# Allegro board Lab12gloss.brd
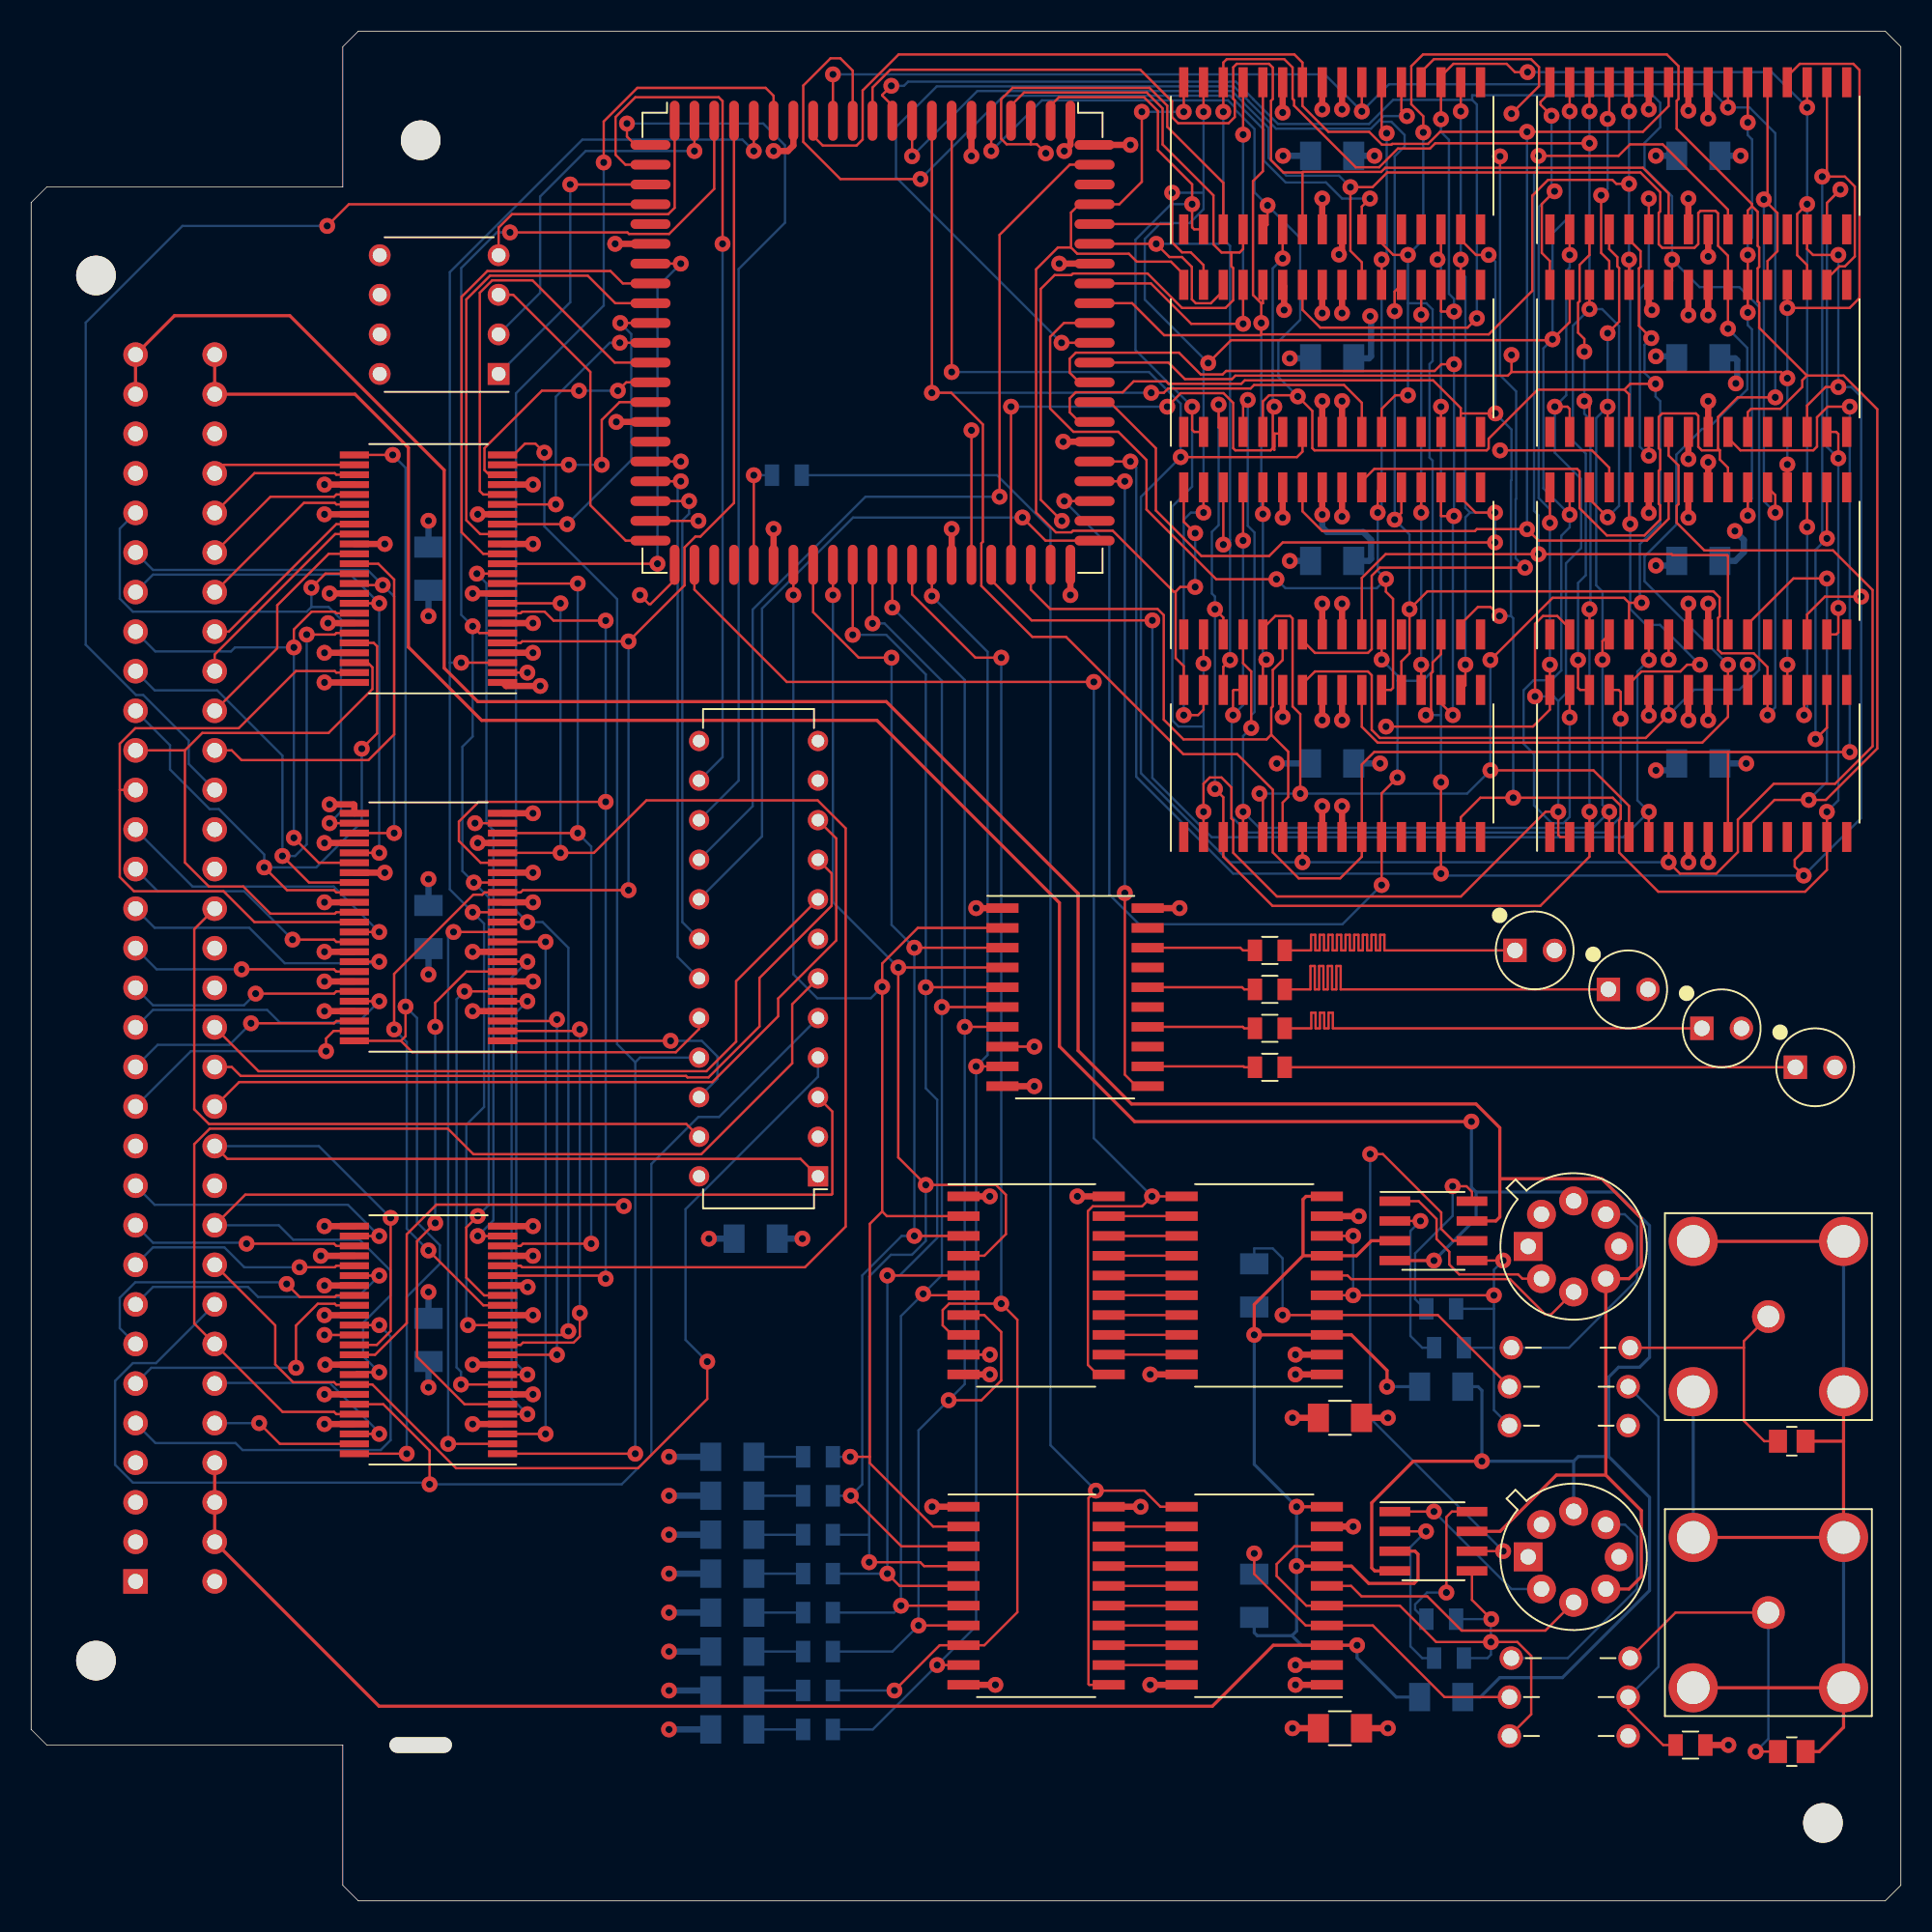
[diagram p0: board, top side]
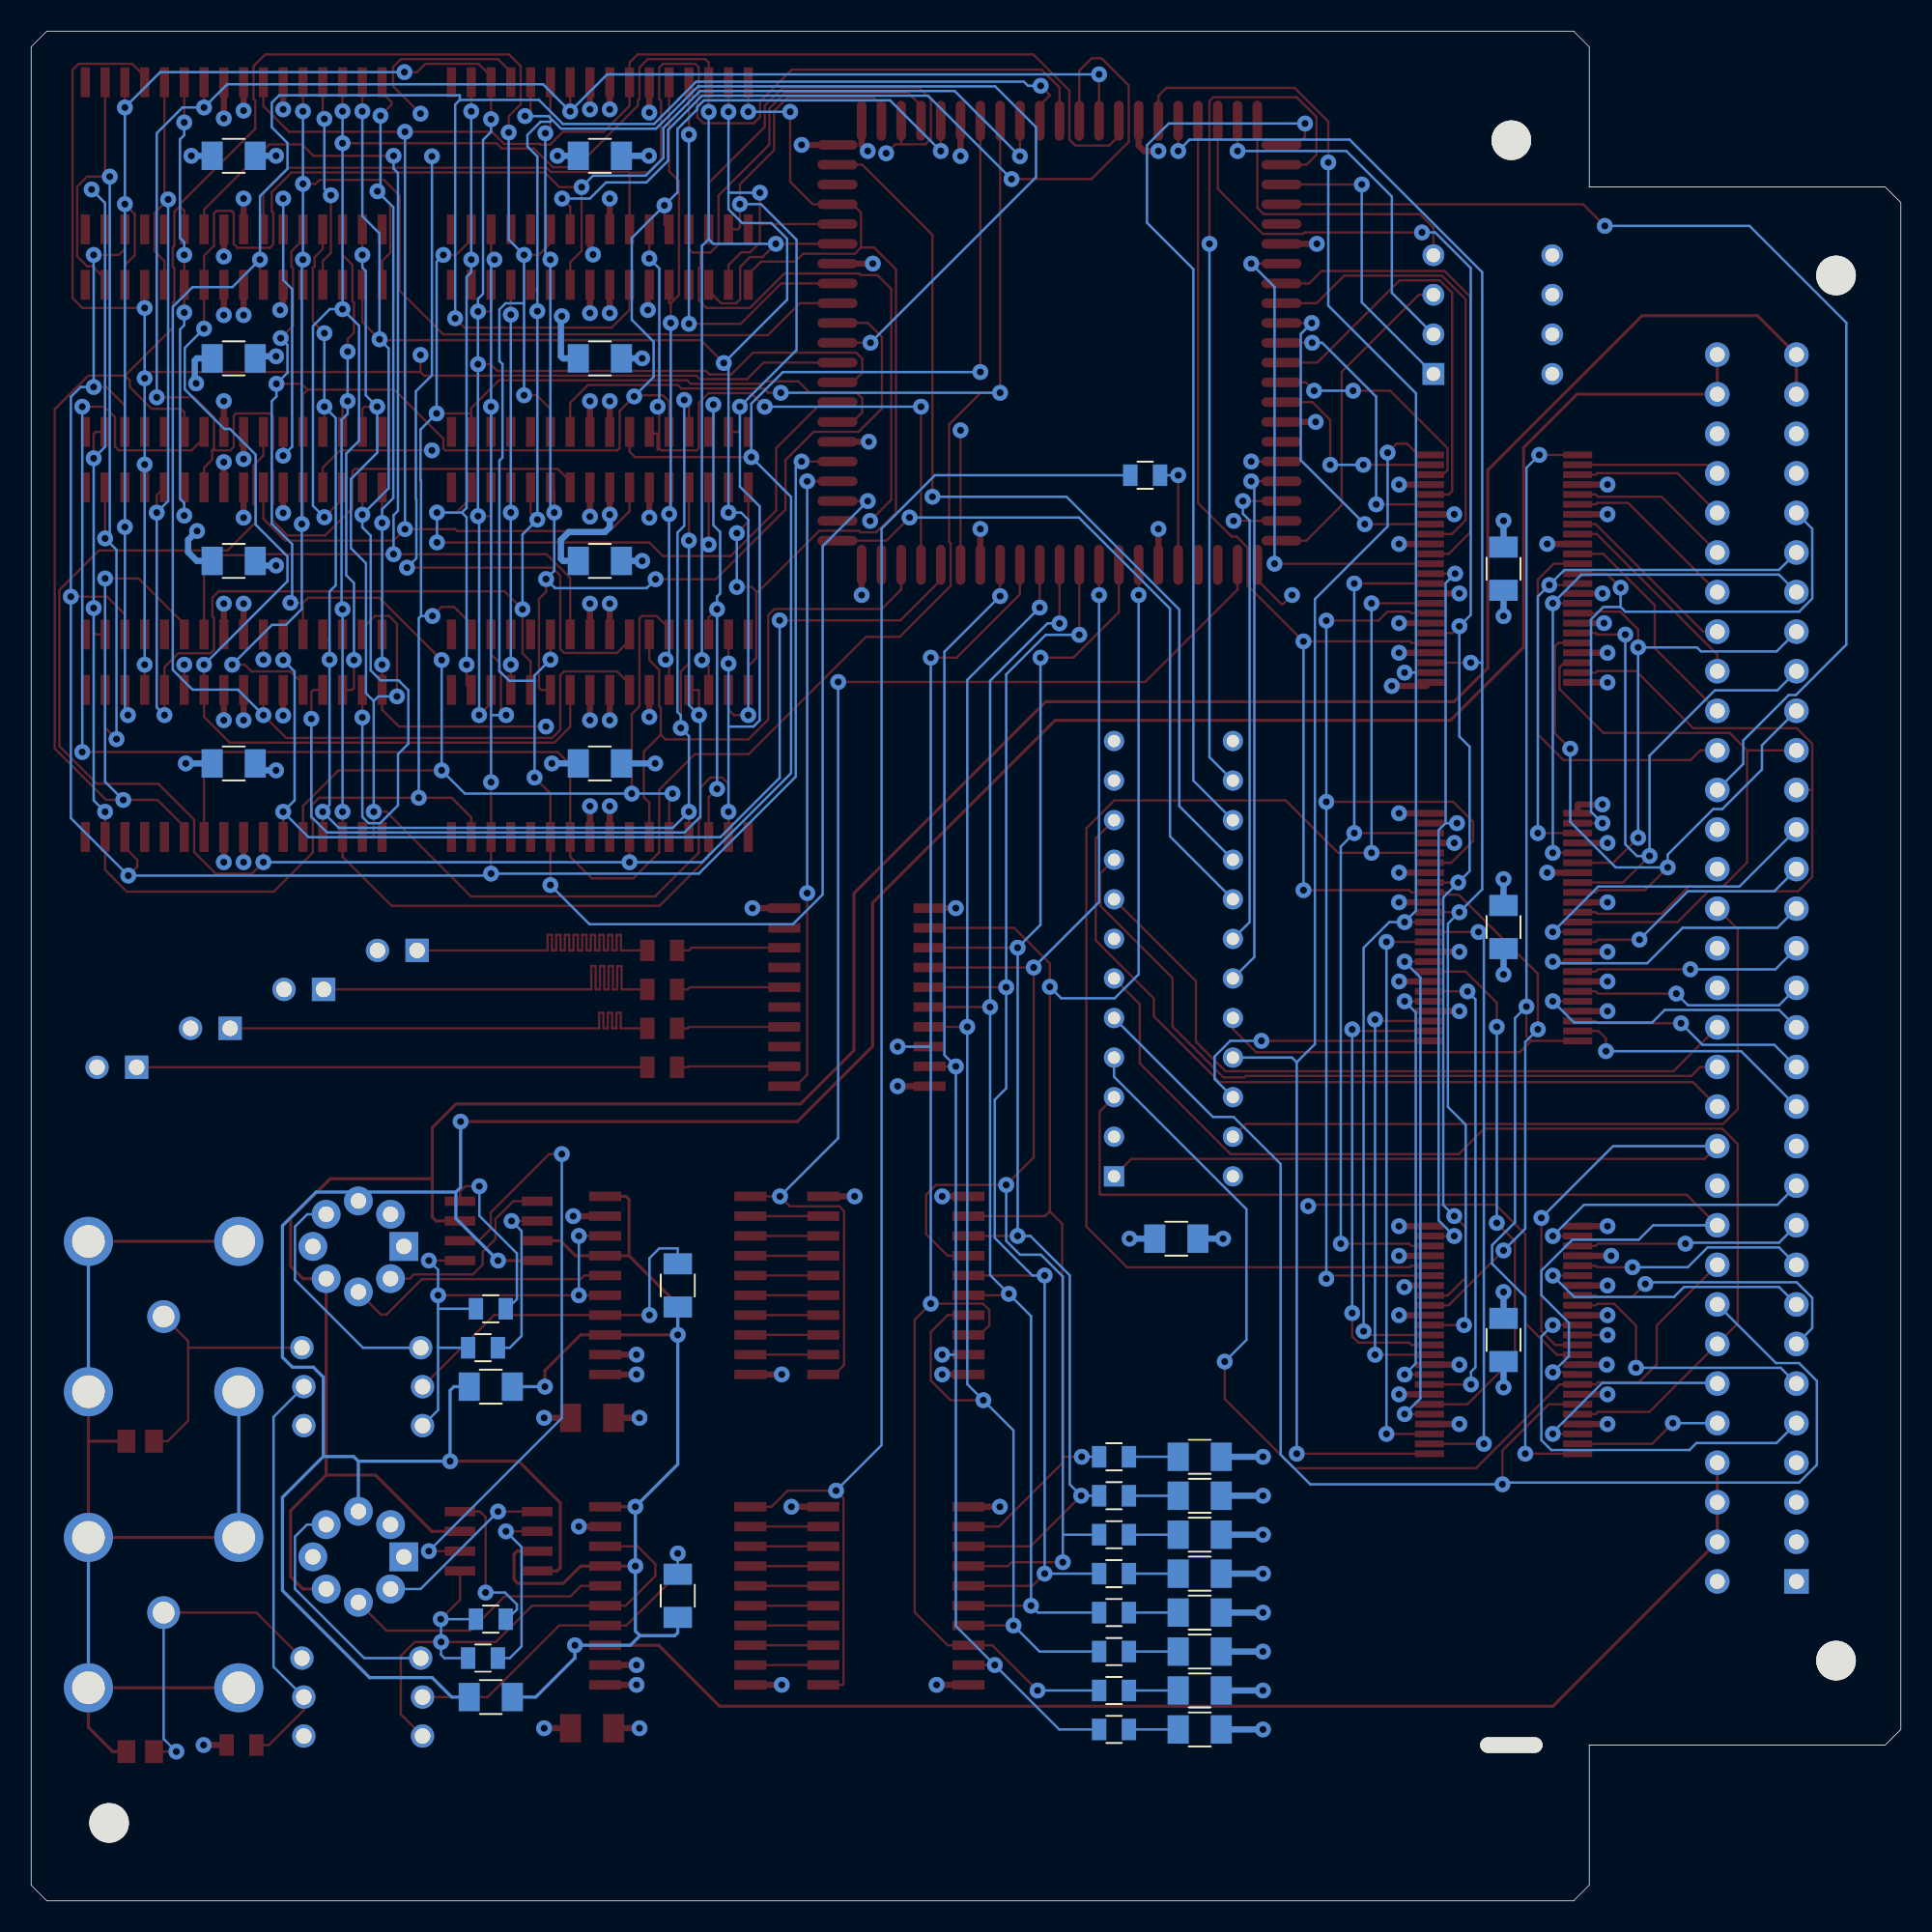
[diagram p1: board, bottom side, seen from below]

Outline 120 x 120 mm; copper layers: TOP, GND, VCC, BOTTOM. Coordinates in mm from the lower left corner of the outline.

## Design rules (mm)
constraint set DEFAULT: min track width 0.15
net group LEDNETS: nets LED1 LED2 LED3 LED4
net group MEMORY[0..28]: nets MEMORY.RA0 MEMORY.RA1 MEMORY.RA2 MEMORY.RA3 MEMORY.RA4 MEMORY.RA5 MEMORY.RA6 MEMORY.RA7 MEMORY.RA8 MEMORY.RA9 MEMORY.RA10 MEMORY.RA11 MEMORY.RA12 MEMORY.RA13 MEMORY.RA14 MEMORY.RA15 MEMORY.RCS0 MEMORY.RCS1 MEMORY.RCS2 MEMORY.RCS3 MEMORY.RD0 MEMORY.RD1 MEMORY.RD2 MEMORY.RD3 MEMORY.RD4 MEMORY.RD5 MEMORY.RD6 MEMORY.RD7 MEMORY.RWE
net group POWER: nets AGND GND_EARTH V12N V+12
nets with their own width: min track width 0.4; nets GND VCC

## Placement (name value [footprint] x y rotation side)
C1  0.1uF  [CAPC3216X110N]  25.5 36 90 bottom
C2  0.1uF  [CAPC3216X110N]  46.5 42.5 0 bottom
C3  0.1uF  [CAPC3216X110N]  25.5 62.5 90 bottom
C4  0.1uF  [CAPC3216X110N]  25.5 85.5 90 bottom
C5  47PF  [CAPC2012X110N]  113 29.5 0 top
C6  47PF  [CAPC2012X110N]  113 9.58 0 top
C7  0.01u  [CAPC3216X110N]  84 31 0 top
C8  0.01u  [CAPC3216X110N]  78.5 39.5 270 bottom
C9  0.1u  [CAPC3216X110N]  90.5 33 180 bottom
C10  0.01u  [CAPC3216X110N]  84 11.08 0 top
C11  0.01u  [CAPC3216X110N]  78.5 19.58 270 bottom
C12  0.1u  [CAPC3216X110N]  90.5 13.08 180 bottom
C13  330p  [CAPC3216X110N]  45 13.5 180 bottom
C14  330p  [CAPC3216X110N]  45 18.5 180 bottom
C15  330p  [CAPC3216X110N]  45 23.5 180 bottom
C16  330p  [CAPC3216X110N]  45 28.5 180 bottom
C17  330p  [CAPC3216X110N]  45 11 180 bottom
C18  330p  [CAPC3216X110N]  45 16 180 bottom
C19  330p  [CAPC3216X110N]  45 21 180 bottom
C20  330p  [CAPC3216X110N]  45 26 180 bottom
C21  0.1uF  [CAPC3216X110N]  83.5 112 0 bottom
C22  0.1uF  [CAPC3216X110N]  107 112 0 bottom
C23  0.1uF  [CAPC3216X110N]  83.5 99 0 bottom
C24  0.1uF  [CAPC3216X110N]  107 99 0 bottom
C25  0.1uF  [CAPC3216X110N]  83.5 86 0 bottom
C26  0.1uF  [CAPC3216X110N]  107 86 0 bottom
C27  0.1uF  [CAPC3216X110N]  107 73 0 bottom
C28  0.1uF  [CAPC3216X110N]  83.5 73 0 bottom
D1  LED  [LEDRD254W00D500H860P]  96.5 61 0 top
D2  LED  [LEDRD254W00D500H860P]  102.5 58.5 0 top
D3  LED  [LEDRD254W00D500H860P]  108.5 56 0 top
D4  LED  [LEDRD254W00D500H860P]  114.5 53.5 0 top
J1  CON64  [DIN64]  6.7 20.5 0 top
J2  BNC  [CONNEX_112659]  111.5 37.5 0 top
J3  BNC  [CONNEX_112659]  111.5 18.5 0 top
L1  47u  [INDAD762W79L381D254P]  95 35.5 0 top
L2  47u  [INDAD762W79L381D254P]  95 15.58 0 top
L3  47u  [INDAD762W79L381D254P]  102.5 33 180 top
L4  47u  [INDAD762W79L381D254P]  102.5 30.5 180 top
L5  47u  [INDAD762W79L381D254P]  102.5 13.08 180 top
L6  47u  [INDAD762W79L381D254P]  102.5 10.58 180 top
NOREF  -  []  119.5 119.5 0 top
NOREF#2  -  []  37.5 0 90 top
NOREF#3  -  []  -74.06 -89.06 0 top
NOREF#4  -  []  25 10 90 top
NOREF#5  -  []  25 10 90 top
NOREF#6  -  []  25 10 0 top
NOREF#7  -  []  25 10 0 top
NOREF#8  -  []  25 10 90 top
NOREF#9  -  []  197.72 157.32 0 top
NOREF#10  -  [unnamed#2]  25 10 0 top
R1  150  [RESC2012X60N]  79.5 61 0 top
R2  150  [RESC2012X60N]  79.5 58.5 0 top
R3  150  [RESC2012X60N]  79.5 56 0 top
R4  150  [RESC2012X60N]  79.5 53.5 0 top
R5  2K  [RESC2012X60N]  48.5 91.5 0 bottom
R6  100  [RESC2012X60N]  90.5 38 180 bottom
R7  100  [RESC2012X60N]  91 35.5 180 bottom
R8  100  [RESC2012X60N]  90.5 18.08 180 bottom
R9  100  [RESC2012X60N]  91 15.58 180 bottom
R10  10K  [RESC2012X60N]  50.5 13.5 0 bottom
R11  10K  [RESC2012X60N]  50.5 18.5 0 bottom
R12  10K  [RESC2012X60N]  50.5 23.5 0 bottom
R13  10K  [RESC2012X60N]  50.5 28.5 0 bottom
R14  10K  [RESC2012X60N]  50.5 11 0 bottom
R15  10K  [RESC2012X60N]  50.5 16 0 bottom
R16  10K  [RESC2012X60N]  50.5 21 0 bottom
R17  10K  [RESC2012X60N]  50.5 26 0 bottom
R18  10K  [RESC2012X60N]  106.5 10 0 top
U1  FCT16245  [SOP63P1035X279-48N]  25.5 36 90 top
U2  20L10  [DIP763W46P254L3204H508Q24P]  50.5 46.5 90 top
U3  FCT16245  [SOP63P1035X279-48N]  25.5 62.5 90 top
U4  FCT16245  [SOP63P1035X279-48N]  25.5 85.5 90 top
U5  EPF8282A_LCC  [PLCC127P3022X3022X457-84N]  54 100 270 top
U6  74ACT574  [SOIC127P1034X264-20N]  67 58 270 top
U7  EPC1064  [DIP763W46P254L991H419Q8P]  30 98 90 top
U8  TLC5602A  [SOIC127P1034X264-20N]  78.5 39.5 90 top
U9  TLE2037A  [TO292P469H584-8P]  99 42 0 top
U10  DG419AK  [SOIC127P600X175-8N]  90 43 270 top
U11  TLC5602A  [SOIC127P1034X264-20N]  78.5 19.58 90 top
U12  TLE2037A  [TO292P469H584-8P]  99 22.08 0 top
U13  DG419AK  [SOIC127P600X175-8N]  90 23.08 270 top
U14  74ACT574  [SOIC127P1034X264-20N]  64.5 39.5 270 top
U15  74ACT574  [SOIC127P1034X264-20N]  64.5 19.58 270 top
U16  TC55B4257  [SOIC127P1032X265-32N]  83.5 73 0 top
U17  TC55B4257  [SOIC127P1032X265-32N]  83.5 86 0 top
U18  TC55B4257  [SOIC127P1032X265-32N]  83.5 99 0 top
U19  TC55B4257  [SOIC127P1032X265-32N]  83.5 112 0 top
U20  TC55B4257  [SOIC127P1032X265-32N]  107 73 0 top
U21  TC55B4257  [SOIC127P1032X265-32N]  107 86 0 top
U22  TC55B4257  [SOIC127P1032X265-32N]  107 99 0 top
U23  TC55B4257  [SOIC127P1032X265-32N]  107 112 0 top

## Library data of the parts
C1-C4 C13-C20 = CAP NP
C5 C7-C9 = CAP NP: room: CHAN1
C6 C10-C12 = CAP NP: room: CHAN2
C21-C28 = CAP NP: room: MEM
D1-D4 = PHOTODIODE_0
J1 = CON64
J2 = BNC: room: CHAN1
J3 = BNC: room: CHAN2
L1 L3 L4 = INDUCTOR: room: CHAN1
L2 L5 L6 = INDUCTOR: room: CHAN2
R1-R4 = R: room: LED
R5 R10-R17 = R
R6 R7 = R: room: CHAN1
R8 R9 R18 = R: room: CHAN2
U1 U3 U4 = FCT16245
U2 = 20L10: alternate symbols: (T:SOIC24;B:SOIC24_PE)
U5 = EPF8282A/LCC
U6 = 74ACT574: room: LED
U7 = EPC1064
U8 = TLC5602A: room: CHAN1
U9 = TLE2037A: room: CHAN1
U10 = DG419AK: room: CHAN1
U11 = TLC5602A: room: CHAN2
U12 = TLE2037A: room: CHAN2
U13 = DG419AK: room: CHAN2
U14 = 74ACT574: room: CHAN1
U15 = 74ACT574: room: CHAN2
U16-U23 = TC55B4257: room: MEM

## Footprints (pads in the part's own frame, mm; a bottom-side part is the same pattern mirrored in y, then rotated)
CAPC2012X110N
  rect 1.15x1.47 smd: 1(-0.885,0) 2(0.885,0)
CAPC3216X110N
  rect 1.35x1.82 smd: 1(-1.385,0) 2(1.385,0)
CONNEX_112659
  round 2.1 hole 1.4: 1(0,0)
  round 3.15 hole 2.1: 2(-4.825,4.825) 3(4.825,4.825) 4(4.825,-4.825) 5(-4.825,-4.825)
DIN64
  round 2.54 hole 2.794 unplated: (-2.54,83.82) (-2.54,-5.08)
  rect 1.575x1.575 hole 0.965: 1(0,0)
  round 1.575 hole 0.965: 2(0,2.54) 3(0,5.08) 4(0,7.62) 5(0,10.16) 6(0,12.7) 7(0,15.24) 8(0,17.78) 9(0,20.32) 10(0,22.86) 11(0,25.4) 12(0,27.94) 13(0,30.48) 14(0,33.02) 15(0,35.56) 16(0,38.1) 17(0,40.64) 18(0,43.18) 19(0,45.72) 20(0,48.26) 21(0,50.8) 22(0,53.34) 23(0,55.88) 24(0,58.42) 25(0,60.96) 26(0,63.5) 27(0,66.04) 28(0,68.58) 29(0,71.12) 30(0,73.66) 31(0,76.2) 32(0,78.74) 33(5.08,0) 34(5.08,2.54) 35(5.08,5.08) 36(5.08,7.62) 37(5.08,10.16) 38(5.08,12.7) 39(5.08,15.24) 40(5.08,17.78) 41(5.08,20.32) 42(5.08,22.86) 43(5.08,25.4) 44(5.08,27.94) 45(5.08,30.48) 46(5.08,33.02) 47(5.08,35.56) 48(5.08,38.1) 49(5.08,40.64) 50(5.08,43.18) 51(5.08,45.72) 52(5.08,48.26) 53(5.08,50.8) 54(5.08,53.34) 55(5.08,55.88) 56(5.08,58.42) 57(5.08,60.96) 58(5.08,63.5) 59(5.08,66.04) 60(5.08,68.58) 61(5.08,71.12) 62(5.08,73.66) 63(5.08,76.2) 64(5.08,78.74)
DIP763W46P254L991H419Q8P
  rect 1.4x1.4 hole 0.9: 1(0,0)
  round 1.4 hole 0.9: 2(2.54,0) 3(5.08,0) 4(7.62,0) 5(7.62,7.63) 6(5.08,7.63) 7(2.54,7.63) 8(0,7.63)
DIP763W46P254L3204H508Q24P
  rect 1.3x1.3 hole 0.8: 1(0,0)
  round 1.3 hole 0.8: 2(2.54,0) 3(5.08,0) 4(7.62,0) 5(10.16,0) 6(12.7,0) 7(15.24,0) 8(17.78,0) 9(20.32,0) 10(22.86,0) 11(25.4,0) 12(27.94,0) 13(27.94,7.63) 14(25.4,7.63) 15(22.86,7.63) 16(20.32,7.63) 17(17.78,7.63) 18(15.24,7.63) 19(12.7,7.63) 20(10.16,7.63) 21(7.62,7.63) 22(5.08,7.63) 23(2.54,7.63) 24(0,7.63)
INDAD762W79L381D254P
  round 1.5 hole 1: 1(0,0) 2(7.62,0)
LEDRD254W00D500H860P
  round 1.5 hole 1: A(1.27,0)
  rect 1.5x1.5 hole 1: C(-1.27,0)
PLCC127P3022X3022X457-84N
  oval 2.57x0.62 smd: 1(-14.25,0) 2(-14.25,-1.27) 3(-14.25,-2.54) 4(-14.25,-3.81) 5(-14.25,-5.08) 6(-14.25,-6.35) 7(-14.25,-7.62) 8(-14.25,-8.89) 9(-14.25,-10.16) 10(-14.25,-11.43) 11(-14.25,-12.7) 33(14.25,-12.7) 34(14.25,-11.43) 35(14.25,-10.16) 36(14.25,-8.89) 37(14.25,-7.62) 38(14.25,-6.35) 39(14.25,-5.08) 40(14.25,-3.81) 41(14.25,-2.54) 42(14.25,-1.27) 43(14.25,0) 44(14.25,1.27) 45(14.25,2.54) 46(14.25,3.81) 47(14.25,5.08) 48(14.25,6.35) 49(14.25,7.62) 50(14.25,8.89) 51(14.25,10.16) 52(14.25,11.43) 53(14.25,12.7) 75(-14.25,12.7) 76(-14.25,11.43) 77(-14.25,10.16) 78(-14.25,8.89) 79(-14.25,7.62) 80(-14.25,6.35) 81(-14.25,5.08) 82(-14.25,3.81) 83(-14.25,2.54) 84(-14.25,1.27)
  oval 0.62x2.57 smd: 12(-12.7,-14.25) 13(-11.43,-14.25) 14(-10.16,-14.25) 15(-8.89,-14.25) 16(-7.62,-14.25) 17(-6.35,-14.25) 18(-5.08,-14.25) 19(-3.81,-14.25) 20(-2.54,-14.25) 21(-1.27,-14.25) 22(0,-14.25) 23(1.27,-14.25) 24(2.54,-14.25) 25(3.81,-14.25) 26(5.08,-14.25) 27(6.35,-14.25) 28(7.62,-14.25) 29(8.89,-14.25) 30(10.16,-14.25) 31(11.43,-14.25) 32(12.7,-14.25) 54(12.7,14.25) 55(11.43,14.25) 56(10.16,14.25) 57(8.89,14.25) 58(7.62,14.25) 59(6.35,14.25) 60(5.08,14.25) 61(3.81,14.25) 62(2.54,14.25) 63(1.27,14.25) 64(0,14.25) 65(-1.27,14.25) 66(-2.54,14.25) 67(-3.81,14.25) 68(-5.08,14.25) 69(-6.35,14.25) 70(-7.62,14.25) 71(-8.89,14.25) 72(-10.16,14.25) 73(-11.43,14.25) 74(-12.7,14.25)
RESC2012X60N
  rect 0.92x1.38 smd: 1(-0.955,0) 2(0.955,0)
SOIC127P600X175-8N
  rect 0.6x1.97 smd: 1(-1.905,-2.475) 2(-0.635,-2.475) 3(0.635,-2.475) 4(1.905,-2.475) 5(1.905,2.475) 6(0.635,2.475) 7(-0.635,2.475) 8(-1.905,2.475)
SOIC127P1032X265-32N
  rect 0.59x1.92 smd: 1(-9.525,-4.72) 2(-8.255,-4.72) 3(-6.985,-4.72) 4(-5.715,-4.72) 5(-4.445,-4.72) 6(-3.175,-4.72) 7(-1.905,-4.72) 8(-0.635,-4.72) 9(0.635,-4.72) 10(1.905,-4.72) 11(3.175,-4.72) 12(4.445,-4.72) 13(5.715,-4.72) 14(6.985,-4.72) 15(8.255,-4.72) 16(9.525,-4.72) 17(9.525,4.72) 18(8.255,4.72) 19(6.985,4.72) 20(5.715,4.72) 21(4.445,4.72) 22(3.175,4.72) 23(1.905,4.72) 24(0.635,4.72) 25(-0.635,4.72) 26(-1.905,4.72) 27(-3.175,4.72) 28(-4.445,4.72) 29(-5.715,4.72) 30(-6.985,4.72) 31(-8.255,4.72) 32(-9.525,4.72)
SOIC127P1034X264-20N
  rect 0.61x2.06 smd: 1(-5.715,-4.66) 2(-4.445,-4.66) 3(-3.175,-4.66) 4(-1.905,-4.66) 5(-0.635,-4.66) 6(0.635,-4.66) 7(1.905,-4.66) 8(3.175,-4.66) 9(4.445,-4.66) 10(5.715,-4.66) 11(5.715,4.66) 12(4.445,4.66) 13(3.175,4.66) 14(1.905,4.66) 15(0.635,4.66) 16(-0.635,4.66) 17(-1.905,4.66) 18(-3.175,4.66) 19(-4.445,4.66) 20(-5.715,4.66)
SOP63P1035X279-48N
  rect 0.44x1.87 smd: 1(-7.302,-4.755) 2(-6.668,-4.755) 3(-6.032,-4.755) 4(-5.398,-4.755) 5(-4.762,-4.755) 6(-4.128,-4.755) 7(-3.492,-4.755) 8(-2.858,-4.755) 9(-2.222,-4.755) 10(-1.588,-4.755) 11(-0.952,-4.755) 12(-0.318,-4.755) 13(0.318,-4.755) 14(0.952,-4.755) 15(1.588,-4.755) 16(2.222,-4.755) 17(2.858,-4.755) 18(3.492,-4.755) 19(4.128,-4.755) 20(4.762,-4.755) 21(5.398,-4.755) 22(6.032,-4.755) 23(6.668,-4.755) 24(7.302,-4.755) 25(7.302,4.755) 26(6.668,4.755) 27(6.032,4.755) 28(5.398,4.755) 29(4.762,4.755) 30(4.128,4.755) 31(3.492,4.755) 32(2.858,4.755) 33(2.222,4.755) 34(1.588,4.755) 35(0.952,4.755) 36(0.318,4.755) 37(-0.318,4.755) 38(-0.952,4.755) 39(-1.588,4.755) 40(-2.222,4.755) 41(-2.858,4.755) 42(-3.492,4.755) 43(-4.128,4.755) 44(-4.762,4.755) 45(-5.398,4.755) 46(-6.032,4.755) 47(-6.668,4.755) 48(-7.302,4.755)
TO292P469H584-8P
  rect 1.85x1.85 hole 1: 1(-2.921,0)
  round 1.85 hole 1: 2(-2.066,-2.066) 3(0,-2.921) 4(2.066,-2.066) 5(2.921,0) 6(2.066,2.066) 7(0,2.921) 8(-2.066,2.066)
unnamed#2
  round 2.54 hole 2.794 unplated: (0,103) (90,-5)
  oval 4x1 hole 5x1.5 unplated: (0,0)

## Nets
AGND: C8.2 C9.2 C11.2 C12.2 J1.34 J1.35 J1.36 U8.3 U8.7 U8.10 U10.3 U11.3 U11.7 U11.10 U13.3
GND: C1.2 C2.2 C3.2 C4.2 C7.2 C10.2 C13.2 C14.2 C15.2 C16.2 C17.2 C18.2 C19.2 C20.2 C21.2 C22.2 C23.2 C24.2 C25.2 C26.2 C27.2 C28.2 J1.1 J1.2 J1.3 J1.33 R18.2 U1.4 U1.10 U1.15 U1.21 U1.24 U1.25(G\) U1.28 U1.34 U1.39 U1.45 U2.11 U2.12 U2.13 U3.4 U3.10 U3.15 U3.21 U3.24 U3.25(G\) U3.28 U3.34 U3.39 U3.45 U4.1 U4.4 U4.10 U4.15 U4.21 U4.28 U4.34 U4.39 U4.45 U4.48 U5.5 U5.26 U5.47 U5.53 U5.68 U5.74 U5.75 U6.1 U6.10 U7.5 U8.1 U8.20 U11.1 U11.20 U14.1 U14.10 U15.1 U15.10 U16.9 U16.25 U16.27 U17.9 U17.25 U17.27 U18.9 U18.25 U18.27 U19.9 U19.25 U19.27 U20.9 U20.25 U20.27 U21.9 U21.25 U21.27 U22.9 U22.25 U22.27 U23.9 U23.25 U23.27
GND_EARTH: C5.2 C6.2 J2.2 J2.3 J2.4 J2.5(GND5) J3.2 J3.3 J3.4 J3.5(GND5)
V12N: J1.31 J1.32 U9.4(V-) U10.7 U12.4(V-) U13.7
VCC: C1.1 C2.1 C3.1 C4.1 C7.1 C10.1 C21.1 C22.1 C23.1 C24.1 C25.1 C26.1 C27.1 C28.1 D1.A D2.A D3.A D4.A J1.29 J1.30 J1.62 L4.1 L6.1 U1.7 U1.18 U1.31 U1.42 U2.24(VCC) U3.7 U3.18 U3.31 U3.42 U4.7 U4.18 U4.31 U4.42 U5.17 U5.38 U5.59 U5.80 U6.20 U7.7 U7.8 U8.2 U8.9(VD2) U11.2 U11.9(VD2) U14.20 U15.20 U16.8 U16.24 U17.8 U17.24 U18.8 U18.24 U19.8 U19.24 U20.8 U20.24 U21.8 U21.24 U22.8 U22.24 U23.8 U23.24
A0: J1.54 U4.36
A1: J1.55 U4.35
A2: J1.56 U4.33
A3: J1.57 U4.32
A4: J1.58 U4.30
A5: J1.59 U4.29
A6: J1.60 U4.27
A7: J1.61 U4.26
A8: J1.13 U3.47
A9: J1.14 U3.46
A10: J1.15 U3.44
A11: J1.16 U3.43
A12: J1.17 U3.41
A13: J1.18 U3.40
A14: J1.19 U3.38
A15: J1.20 U3.37
A16: J1.37 U1.47
A17: J1.38 U1.46
A18: J1.39 U1.44 U2.6
A19: J1.40 U1.43 U2.5
A20: J1.41 U1.41 U2.4
A21: J1.42 U1.40 U2.3
A22: J1.43 U1.38 U2.2
A23: J1.44 U1.37 U2.1
AEN: J1.47 U2.8
BA0: U1.13 U3.13 U4.2 U5.6
BA1: U1.14 U3.14 U4.3 U5.7
BA2: U1.16 U3.16 U4.5 U5.8
BA3: U1.17 U3.17 U4.6 U5.9
BA4: U1.19 U3.19 U4.8
BA5: U1.20 U3.20 U4.9
BA6: U1.22 U3.22 U4.11
BA7: U1.23 U3.23 U4.12
BD0: U4.23 U5.25
BD1: U4.22 U5.24
BD2: U4.20 U5.23
BD3: U4.19 U5.22
BD4: U4.17 U5.21
BD5: U4.16 U5.20
BD6: U4.14 U5.19
BD7: U4.13 U5.18
BD8: U1.12 U3.2
BD9: U1.11 U3.3
BD10: U1.9 U3.5
BD11: U1.8 U3.6
BD12: U1.6 U3.8
BD13: U1.5 U3.9
BD14: U1.3 U3.11
BD15: U1.2 U3.12
BNC2: C5.1 J2.1 L1.2
BNC3: C6.1 J3.1 L2.2
BRD: U2.16 U5.73
BRESET: U2.15 U5.12
BWR: U2.17 U5.54
D0: J1.28 U3.26 U4.37
D1: J1.27 U3.27 U4.38
D2: J1.26 U3.29 U4.40
D3: J1.25 U3.30 U4.41
D4: J1.24 U3.32 U4.43
D5: J1.23 U3.33 U4.44
D6: J1.22 U3.35 U4.46
D7: J1.21 U3.36 U4.47
D8: J1.4 U1.36
D9: J1.5 U1.35
D10: J1.6 U1.33
D11: J1.7 U1.32
D12: J1.8 U1.30
D13: J1.9 U1.29
D14: J1.10 U1.27
D15: J1.11 U1.26
DATA: U5.14 U7.1
DCLK: U5.10 U7.2
DDIR: U1.48 U2.20 U3.48 U4.25(G\)
DEN: U1.1 U2.21 U4.24
DHEN: U2.22 U3.1
FPGA: U2.18 U5.30
GAIN: U5.28 U10.6 U13.6
HS: U2.19 U5.29
LED1: D1.C(CATHODE) R1.2
LED2: D2.C(CATHODE) R2.2
LED3: D3.C(CATHODE) R3.2
LED4: D4.C(CATHODE) R4.2
MCLK: J1.52 U5.31
MEMORY.RA0: U5.79 U16.5 U17.5 U18.5 U19.5 U20.5 U21.5 U22.5 U23.5
MEMORY.RA1: U5.78 U16.4 U17.4 U18.4 U19.4 U20.4 U21.4 U22.4 U23.4
MEMORY.RA2: U5.77 U16.3 U17.3 U18.3 U19.3 U20.3 U21.3 U22.3 U23.3
MEMORY.RA3: U5.76 U16.2 U17.2 U18.2 U19.2 U20.2 U21.2 U22.2 U23.2
MEMORY.RA4: U5.71 U16.32 U17.32 U18.32 U19.32 U20.32 U21.32 U22.32 U23.32
MEMORY.RA5: U5.70 U16.31 U17.31 U18.31 U19.31 U20.31 U21.31 U22.31 U23.31
MEMORY.RA6: U5.69 U16.30 U17.30 U18.30 U19.30 U20.30 U21.30 U22.30 U23.30
MEMORY.RA7: U5.67 U16.29 U17.29 U18.29 U19.29 U20.29 U21.29 U22.29 U23.29
MEMORY.RA8: U5.66 U16.28 U17.28 U18.28 U19.28 U20.28 U21.28 U22.28 U23.28
MEMORY.RA9: U5.65 U16.22 U17.22 U18.22 U19.22 U20.22 U21.22 U22.22 U23.22
MEMORY.RA10: U5.64 U16.21 U17.21 U18.21 U19.21 U20.21 U21.21 U22.21 U23.21
MEMORY.RA11: U5.63 U16.20 U17.20 U18.20 U19.20 U20.20 U21.20 U22.20 U23.20
MEMORY.RA12: U5.62 U16.19 U17.19 U18.19 U19.19 U20.19 U21.19 U22.19 U23.19
MEMORY.RA13: U5.61 U16.18 U17.18 U18.18 U19.18 U20.18 U21.18 U22.18 U23.18
MEMORY.RA14: U5.60 U16.15 U17.15 U18.15 U19.15 U20.15 U21.15 U22.15 U23.15
MEMORY.RA15: U5.58 U16.14 U17.14 U18.14 U19.14 U20.14 U21.14 U22.14 U23.14
MEMORY.RCS0: U5.51 U16.6 U17.6
MEMORY.RCS1: U5.50 U18.6 U19.6
MEMORY.RCS2: U5.49 U20.6 U21.6
MEMORY.RCS3: U5.48 U22.6 U23.6
MEMORY.RD0: U5.81 U16.7 U18.7 U20.7 U22.7
MEMORY.RD1: U5.82 U16.10 U18.10 U20.10 U22.10
MEMORY.RD2: U5.83 U16.23 U18.23 U20.23 U22.23
MEMORY.RD3: U5.84 U16.26 U18.26 U20.26 U22.26
MEMORY.RD4: U5.1 U17.7 U19.7 U21.7 U23.7
MEMORY.RD5: U5.2 U17.10 U19.10 U21.10 U23.10
MEMORY.RD6: U5.3 U17.23 U19.23 U21.23 U23.23
MEMORY.RD7: U5.4 U17.26 U19.26 U21.26 U23.26
MEMORY.RWE: U5.56 U16.11(W\E\) U17.11(W\E\) U18.11(W\E\) U19.11(W\E\) U20.11(W\E\) U21.11(W\E\) U22.11(W\E\) U23.11(W\E\)
MRD: J1.46 U2.9
MWR: J1.45 U2.10
N00036_DATA_DAAMP: L4.2 R6.1 R7.1 U8.5 U8.8 U10.5(VL)
N00036_DATA_DAAMP1: L6.2 R8.1 R9.1 U11.5 U11.8 U13.5(VL)
N00038_DATA_DAAMP: C8.1 L3.2 U8.4
N00038_DATA_DAAMP1: C11.1 L5.2 U11.4
N00044_DATA_DAAMP: U9.2 U10.1
N00044_DATA_DAAMP1: U12.2 U13.1
N00060_DATA_DAAMP: U8.6 U9.3
N00060_DATA_DAAMP1: U11.6 U12.3
N282866_DATA_DAAMP: R6.2 U10.8
N282866_DATA_DAAMP1: R8.2 U13.8
N282912_DATA_DAAMP: R7.2 U10.2
N282912_DATA_DAAMP1: R9.2 U13.2
NCS: U5.11 U7.4
OE: U5.32 U7.3(OE)
OUTA: L1.1 U9.6
OUTB: L2.1 U12.6
Q0: R1.1 U6.18
Q1: R2.1 U6.16
Q2: R3.1 U6.14
Q3: R4.1 U6.12(Q8)
RDY: J1.50 U2.23
RESET: J1.53 U5.15
SEL: U2.14 U5.13
V+12: C9.1 C12.1 J1.63 J1.64 U9.7 U10.4 U12.7 U13.4
VCLKA: U5.34 U8.11 U14.11
VCLKC: R5.2 U11.11 U15.11
VD0: R13.2 U5.39 U6.2 U14.2 U15.2
VD1: R17.2 U5.40 U6.3 U14.3 U15.3
VD2: R12.2 U5.41 U6.4 U14.4 U15.4
VD3: R16.2 U5.42 U6.5 U14.5 U15.5
VD4: R11.2 U5.43 U6.6 U14.6 U15.6
VD5: R15.2 U5.44 U6.7 U14.7 U15.7
VD6: R10.2 U5.45 U6.8 U14.8 U15.8
VD7: R14.2 U5.46(VD7) U6.9 U14.9 U15.9
VREF: L3.1 L5.1 R18.1
WAIT: J1.51 U5.33
WSTAT: U5.57 U6.11
N14843: C19.1 R16.1
N14849: C15.1 R12.1
N14853: C20.1 R17.1
N14855: C16.1 R13.1
N15143: C17.1 R14.1
N15151: C13.1 R10.1
N15155: C18.1 R15.1
N15161: C14.1 R11.1
N58063: U8.12 U14.19
N58118: U8.13 U14.18
N58173: U8.14 U14.17
N58228: U8.15 U14.16
N58283: U8.16 U14.15
N58338: U8.17 U14.14
N58393: U8.18 U14.13
N58448: U8.19 U14.12(Q8)
N58834: U11.12 U15.19
N58889: U11.13 U15.18
N58944: U11.14 U15.17
N58999: U11.15 U15.16
N59054: U11.16 U15.15
N59109: U11.17 U15.14
N59164: U11.18 U15.13
N59219: U11.19 U15.12(Q8)
N409523: R5.1 U5.37

Pads without a net: J1 12 48 49; U2 7; U5 16 27 35 36 52 55 72; U6 13 15 17 19; U7 6; U9 1 5 8; U12 1 5 8; U16 1 12 13 16 17; U17 1 12 13 16 17; U18 1 12 13 16 17; U19 1 12 13 16 17; U20 1 12 13 16 17; U21 1 12 13 16 17; U22 1 12 13 16 17; U23 1 12 13 16 17

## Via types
v1: diameter 1.016, hole 0.457, TOP to BOTTOM, 501 vias

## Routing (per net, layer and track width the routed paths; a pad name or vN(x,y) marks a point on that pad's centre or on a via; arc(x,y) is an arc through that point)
AGND: length 164.5
  TOP w0.2: U11.10 v1(81.22,25.29) ; v1(85.1,16.4) U11.3 79.73,16.4 75.81,12.49 22.33,12.49 J1.34 J1.35 J1.36 ; 81.63,41.41 78.5,38.27 v1(78.5,36.33) U8.3 84.74,36.33 87.02,34.04 v1(87.02,33) ; 81.63,41.41 U8.7 85.06,41.41 86.02,42.37 U10.3 ; 81.63,41.41 81.63,45.02 81.83,45.22 U8.10 ; v1(81.22,21.48) U11.7 84.73,21.48 85.84,20.37 88.76,20.37 89.01,20.63 89.01,22.25 88.81,22.44 U13.3
  BOTTOM w0.2: C9.2 v1(87.02,33) ; C8.2 v1(78.5,36.33) 78.5,28.02 v1(81.22,25.29) v1(81.22,21.48) 81.22,17.32 80.92,17.02 ; C12.2 87.61,13.08 85.1,15.59 v1(85.1,16.4) 81.54,16.4 80.92,17.02 ; C11.2 78.5,17.21 78.69,17.02 80.92,17.02
GND: length 192.9
  TOP w0.4: v1(81.15,13.86) U11.1 ; U5.75 66.7,112.7 v1(66.31,112.31) ; v1(32.21,80.1) U4.4 ; v1(65.98,105.08) U5.68 ; v1(32.21,41.4) U1.21 ; v1(82.87,75.78) U16.25 ; v1(18.83,37.59) U1.34 ; v1(81.15,33.78) U8.1 ; 30.25,78.2 30.48,77.97 v1(32.67,77.97) ; v1(28.34,60.91) U3.10 ; v1(61.53,45.22) U14.1 ; v1(64.39,52.28) U6.10 ; v1(70.55,112.7) U5.74 ; v1(57.83,25.29) U15.1 ; v1(84.13,83.26) U17.9 ; v1(32.21,69.8) U3.24 ; v1(84.13,96.26) U18.9 ; v1(106.36,114.9) U23.25 ; v1(107.64,105.54) U23.9 ; v1(82.87,101.91) U18.25 ; v1(32.21,90.9) U4.21 ; v1(18.83,78.2) U4.48 ; v1(59.08,88.05) U5.47 ; v1(107.64,96.26) U22.9 ; v1(28.34,57.1) U3.4 ; v1(18.83,90.9) U4.28 ; v1(80.33,88.78) U17.27 ; v1(107.64,66.66) U20.9 ; v1(28.66,67.9) U3.21 ; v1(103.83,89.08) U21.27 ; v1(32.21,43.3) U1.24 ; v1(82.87,114.98) U19.25 ; v1(28.34,30.6) U1.4 ; v1(108.93,10) R18.2 ; v1(37.56,94.92) U5.26 ; v1(60.65,63.72) U6.1 ; v1(103.83,76.08) U20.27 ; v1(61.89,13.86) U15.10 ; v1(18.83,80.1) U4.45 ; v1(61.53,33.78) U14.10 ; v1(107.64,83.26) U21.9 ; v1(103.83,114.98) U23.27 ; v1(106.36,75.78) U20.25 ; v1(71.83,33.78) U8.20 ; v1(18.83,60.91) U3.39 ; v1(82.87,88.97) U17.25 ; U22.27 103.83,102.3 v1(104.02,102.1) ; v1(18.83,64.09) U3.34 ; v1(106.36,101.78) U22.25 ; v1(32.21,64.09) U3.15 ; v1(32.21,87.09) U4.15 ; v1(18.83,43.3) 20.75,43.3 ; v1(18.83,57.1) U3.45 ; v1(106.36,88.78) U21.25 ; v1(18.83,67.9) U3.28 ; U5.5 48.92,112.66 48.57,112.31 v1(47.65,112.31) ; v1(66.7,83.81) U5.53 ; U19.9 84.13,105.86 v1(83.94,105.66) ; v1(22.7,87.09) U4.34 ; v1(80.33,75.98) U16.27 ; U18.27 80.42,103.63 v1(80.42,102.1) ; v1(18.83,30.6) U1.45 ; v1(71.83,13.86) U11.20 ; v1(19.15,83.91) U4.39 ; v1(18.87,34.41) U1.39 ; v1(87.08,11.08) C10.2 ; v1(32.21,37.59) U1.15 ; v1(80.33,114.78) U19.27 ; v1(19.15,70.37) 20.7,70.37 20.75,70.33 20.75,69.8 ; v1(28.34,83.91) U4.10 ; v1(84.13,70.26) U16.9 ; v1(87.08,31) C7.2 ; v1(28.34,34.41) U1.10 ; v1(18.59,41.4) U1.28
  BOTTOM w0.4: v1(40.94,18.5) C14.2 ; v1(86.22,112) C21.2 ; v1(40.94,13.5) C13.2 ; v1(86.58,73) C28.2 ; v1(40.94,26) C20.2 ; v1(110.08,73) C27.2 ; v1(49.5,42.5) C2.2 ; v1(40.94,16) C18.2 ; v1(109.35,87.92) 109.93,87.34 109.93,86.56 109.36,86 C26.2 ; v1(82.87,88.97) 82.87,88.16 83.17,87.85 85.49,87.85 86,87.34 86,86.14 85.87,86 C25.2 ; C23.2 85.87,99 86,99.14 86,101.65 v1(85.94,101.7) ; v1(109.41,97.39) 109.5,97.48 109.5,98.86 109.36,99 C24.2 ; v1(25.5,65.58) C3.2 ; v1(25.5,39.08) C1.2 ; v1(40.94,21) C19.2 ; v1(40.94,28.5) C16.2 ; v1(109.72,112) C22.2 ; v1(40.94,11) C17.2 ; v1(25.5,88.58) C4.2 ; v1(40.94,23.5) C15.2
GND_EARTH: length 75
  TOP w0.2: 116.33,29.5 J3.3 J3.2 ; 116.33,29.5 J2.4 ; 116.33,29.5 C5.2 ; J3.5 J3.4 116.33,11.14 114.77,9.58 C6.2 ; J2.2 J2.3
  BOTTOM w0.2: J2.3 J2.4 ; J3.3 J3.4 ; J2.5 J3.2
V12N: length 182.3
  TOP w0.2: 101.07,20.01 102.55,20.01 103.35,20.81 103.35,25.05 101.07,27.32 ; U13.7 94.28,23.71 97.89,27.32 101.07,27.32 ; U10.7 94.01,43.63 94.26,43.89 94.26,46.35 ; 94.26,46.35 94.26,49.62 92.74,51.14 70.62,51.14 67.19,54.57 67.19,64.66 54.89,76.97 28.67,76.97 26.51,79.12 26.51,91.83 16.6,101.74 9.2,101.74 J1.32 J1.31 ; 94.26,46.35 100.81,46.35 103.35,43.81 103.35,40.73 102.55,39.93 U9.4 101.07,27.32
VCC: length 97.7
  TOP w0.4: v1(85.21,43.95) U8.9 ; v1(18.83,88.99) U4.31 ; v1(67.15,45.22) U14.20 ; v1(81.15,35.05) U8.2 ; v1(80.96,31) C7.1 ; v1(81.15,15.13) U11.2 ; v1(82.87,83.26) U17.8 ; v1(37.48,106.35) U5.17 ; v1(107.64,75.78) U20.24 ; v1(106.36,83.26) U21.8 ; v1(18.83,32.51) U1.42 ; v1(47.65,88.05) U5.38 ; v1(84.85,24.02) U11.9 ; v1(82.87,70.26) U16.8 ; v1(84.13,114.98) U19.24 ; v1(73.71,63.72) U6.20 ; U1.18 31.77,39.49 v1(31.87,39.39) ; v1(18.83,39.49) U1.31 ; v1(22.7,65.99) U3.31 ; v1(82.87,96.26) U18.8 ; v1(32.21,82.01) U4.7 ; v1(71.21,25.29) U15.20 ; v1(66.24,93.65) U5.59 ; v1(106.36,66.66) U20.8 ; v1(107.64,114.4) U23.24 ; v1(60.35,111.98) U5.80 ; v1(107.64,92.34) U21.24 ; v1(106.36,109.26) U23.8 ; v1(80.96,11.08) C10.1 ; v1(107.64,101.78) U22.24 ; v1(84.13,101.91) U18.24 ; v1(32.21,65.99) U3.18 ; v1(106.36,92.54) U22.8 ; v1(82.87,109.26) U19.8 ; v1(32.21,59.01) U3.7 ; v1(84.13,75.78) U16.24 ; v1(28.66,88.99) U4.18 ; v1(18.83,59.01) U3.42 ; v1(19.05,82.01) U4.42 ; v1(32.21,32.51) U1.7 ; v1(84.13,88.85) U17.24
  BOTTOM w0.4: C24.1 105.48,99.13 v1(104.28,99.13) ; C27.1 105.17,72.56 v1(104.28,72.56) ; v1(104.28,85.7) 105.31,85.7 C26.1 ; v1(25.5,82.46) C4.1 ; v1(104.28,112) C22.1 ; v1(43.5,42.5) C2.1 ; v1(80.78,86) C25.1 ; v1(80.35,112) C21.1 ; v1(25.5,32.96) C1.1 ; v1(79.95,73) C28.1 ; v1(80.78,99) C23.1 ; v1(25.5,59.46) C3.1
A0: length 25.4
  TOP w0.15: U4.36 22.28,85.82 23.3,84.8 23.3,74.86 21.65,73.21 13.5,73.21 12.87,73.84 J1.54
A1: length 14.8
  TOP w0.15: U4.35 19.09,86.45 15.79,83.15 15.79,80.39 J1.55
A2: length 13.2
  TOP w0.15: J1.56 11.78,79.99 19.51,87.72 U4.33
A3: length 11.8
  TOP w0.15: U4.32 19.59,88.36 12.69,81.46 J1.57
A4: length 11.4
  TOP w0.15: J1.58 17.5,89.72 19.49,89.72 19.59,89.63 U4.30
A5: length 10.5
  TOP w0.15: J1.59 15.36,90.12 19.44,90.12 19.59,90.26 U4.29
A6: length 10.1
  TOP w0.15: U4.27 19.59,91.53 19.49,91.63 14.33,91.63 J1.60
A7: length 9.2
  TOP w0.15: J1.61 12.33,92.17 20.75,92.17
A8: length 16.5
  TOP w0.15: U3.47 19.41,55.83 18.93,55.35 v1(18.93,54.53)
  BOTTOM w0.15: J1.13 10.25,54.53 v1(18.93,54.53)
A9: length 15.3
  TOP w0.15: v1(14.11,56.32) 19.44,56.32 19.59,56.47 U3.46
  BOTTOM w0.15: v1(14.11,56.32) 12.72,54.94 8.12,54.94 J1.14
A10: length 18.6
  TOP w0.15: U3.44 v1(22.34,57.74)
  BOTTOM w0.15: J1.15 7.82,57.18 15.15,57.18 15.96,56.37 20.97,56.37 v1(22.34,57.74)
A11: length 14.9
  TOP w0.15: v1(14.41,58.23) 19.44,58.23 19.59,58.37 U3.43
  BOTTOM w0.15: v1(14.41,58.23) 13.66,57.48 7.82,57.48 J1.16
A12: length 14.7
  TOP w0.15: U3.41 19.59,59.64 19.44,59.79 v1(13.51,59.79)
  BOTTOM w0.15: v1(13.51,59.79) 8.05,59.79 J1.17
A13: length 18.7
  TOP w0.15: U3.40 v1(22.34,60.28)
  BOTTOM w0.15: J1.18 7.93,62.45 14,62.45 16.28,60.18 22.24,60.18 v1(22.34,60.28)
A14: length 16
  TOP w0.15: U3.38 19.59,61.55 19.44,61.69 v1(16.77,61.69)
  BOTTOM w0.15: v1(16.77,61.69) 13.67,64.8 8.12,64.8 J1.19
A15: length 20
  TOP w0.15: U3.37 v1(22.34,62.18)
  BOTTOM w0.15: J1.20 10.36,65.1 19.42,65.1 v1(22.34,62.18)
A16: length 9.5
  TOP w0.15: v1(14.63,30.66) 15.96,29.33 U1.47
  BOTTOM w0.15: J1.37 v1(14.63,30.66)
A17: length 13.6
  TOP w0.15: U1.46 v1(22.34,29.97)
  BOTTOM w0.15: v1(22.34,29.97) 22.34,30.07 19.16,33.24 11.82,33.24 J1.38
A18: length 72.2
  TOP w0.15: U1.44 19.59,31.24 19.44,31.38 16.14,31.38 J1.39 10.47,37.05 10.47,48.56 11.46,49.56 26.74,49.56 28.38,47.92 43.01,47.92 48.84,53.75 48.84,57.55 U2.6
A19: length 91
  TOP w0.15: v1(25.57,26.73) 25.57,28.9 22.6,31.87 U1.43
  BOTTOM w0.15: U2.5 44.15,50.31 42.82,50.31 39.81,47.29 39.81,28.64 37.9,26.73 v1(25.57,26.73) 25.46,26.84 6.53,26.84 5.39,27.99 5.39,33.37 6.53,34.51 8.01,34.51 J1.40
A20: length 66.3
  TOP w0.15: v1(43.39,34.61) 43.39,32.21 38.95,27.77 27.27,27.77 21.89,33.14 U1.41 19.59,33.14 19.44,33.29 16.81,33.29 15.67,34.43 15.67,36.93 J1.41
  BOTTOM w0.15: v1(43.39,34.61) 42,36 42,44.39 50.5,52.89 U2.4
A21: length 68.9
  TOP w0.15: U1.40 20.89,33.92 v1(22.34,33.92) ; U2.3 51.42,50.66 51.42,45.38 51.37,45.33 13.74,45.33 J1.42
  BOTTOM w0.15: J1.42 15.89,43.36 16.82,42.43 21.09,42.43 23.07,40.45 23.07,38.87 21.31,37.1 21.31,34.95 v1(22.34,33.92)
A22: length 69.9
  TOP w0.15: U1.38 22.07,35.05 24.11,37.08 24.11,42.78 26.01,44.68 37.95,44.68 v1(38.04,44.59)
  GND w0.15: 38.04,46.2 12.08,46.2 J1.43 ; 38.04,46.2 39.98,46.2 40.56,45.62 51.25,45.62 51.38,45.75 51.38,48.16 U2.2 ; 38.04,46.2 v1(38.04,44.59)
A23: length 62.7
  TOP w0.15: v1(23.07,43.83) 23.07,36.57 22.18,35.68 U1.37 ; J1.44 12.6,47.62 49.38,47.62 U2.1
  BOTTOM w0.15: v1(23.07,43.83) 18.47,48.44 J1.44
AEN: length 46.7
  TOP w0.15: U2.8 45.25,59.02 45.25,55.15 43.34,53.24 14.6,53.24 J1.47
BA0: length 103.8
  TOP w0.15: U5.6 47.65,115.85 47.14,116.36 38.91,116.36 36.75,114.2 v1(36.75,111.57) ; U4.2 v1(31.85,78.83) ; v1(34.48,36.56) 34.24,36.32 U1.13 ; U3.13 v1(31.85,62.82)
  BOTTOM w0.15: v1(34.48,36.56) 34.48,61.17 32.83,62.82 v1(31.85,62.82) 31.12,63.55 31.12,78.83 ; 31.12,78.83 v1(31.85,78.83) ; 31.12,78.83 31.12,96.76 36.75,102.39 v1(36.75,111.57)
BA1: length 101.8
  TOP w0.15: U1.14 v1(28.04,36.95) ; U5.7 v1(46.38,112.31) ; U3.14 v1(28.34,63.45) ; U4.3 v1(27.6,79.47)
  BOTTOM w0.15: 26.87,79.47 26.87,104.53 35.38,113.04 45.65,113.04 v1(46.38,112.31) ; 26.87,79.47 v1(27.6,79.47) ; 26.87,79.47 26.87,64.92 v1(28.34,63.45) 29.07,62.72 29.07,50.95 27.93,49.81 27.93,37.06 v1(28.04,36.95)
BA2: length 102.6
  TOP w0.15: v1(23.3,55.93) 23.3,59.5 28.38,64.58 28.95,64.58 29.09,64.72 U3.16 31.41,64.72 31.56,64.87 v1(38.34,64.87) ; v1(25.5,41.74) 29.02,38.22 U1.16 ; U5.8 45.11,89.72 42.95,87.56 42.63,87.56 41.94,86.87 41.94,84.43 v1(38.34,80.83) 31.51,80.83 31.41,80.74 U4.5
  BOTTOM w0.15: v1(23.3,55.93) 24.11,55.12 24.11,43.14 v1(25.5,41.74) ; v1(38.34,64.87) v1(38.34,80.83)
BA3: length 96.2
  TOP w0.15: U3.17 v1(28.41,65.36) ; v1(28.34,81.81) 28.77,81.37 U4.6 ; U1.17 29.07,38.86 27.93,40 27.93,43.22 v1(28.66,43.95) ; U5.9 43.84,109.88 40.95,106.98 38.37,106.98 38.27,107.08 v1(30.73,107.08)
  BOTTOM w0.15: v1(30.73,107.08) 29.89,107.08 27.6,104.8 27.6,82.54 v1(28.34,81.81) 28.34,74.73 27.68,74.07 27.68,66.09 v1(28.41,65.36) 29.37,64.4 29.37,44.66 v1(28.66,43.95)
BA4: length 70.4
  TOP w0.15: v1(36.87,70.53) 28.72,70.53 27.45,69.27 27.45,68.03 28.85,66.63 U3.19 ; U4.8 31.41,82.64 31.51,82.74 32.95,82.74 33.53,82.17 v1(36.87,82.17) ; v1(36.87,39.93) 36.68,40.13 U1.19
  BOTTOM w0.15: v1(36.87,39.93) v1(36.87,70.53) v1(36.87,82.17)
BA5: length 92.6
  TOP w0.15: U4.9 v1(33.97,83.28) ; U3.20 v1(33.97,67.26) 36.12,67.26 39.49,70.63 50.48,70.63 52.27,68.84 52.27,43.28 49.66,40.66 31.51,40.66 31.41,40.76 U1.20
  BOTTOM w0.15: v1(33.97,83.28) v1(33.97,67.26)
BA6: length 58.1
  TOP w0.15: U3.22 v1(35.08,68.53) ; U4.11 v1(35.08,84.55) ; U1.22 31.41,42.03 31.56,42.18 v1(35.95,42.18)
  BOTTOM w0.15: v1(35.95,42.18) 35.95,67.67 v1(35.08,68.53) v1(35.08,84.55)
BA7: length 49.1
  TOP w0.15: U3.23 v1(28.49,69.17) ; U1.23 v1(28.66,42.67) ; U4.12 v1(28.61,85.18)
  BOTTOM w0.15: 29.22,69.17 v1(28.49,69.17) ; 29.22,69.17 29.67,68.72 29.67,43.67 v1(28.66,42.67) ; 29.22,69.17 29.22,84.57 v1(28.61,85.18)
BD0: length 12.8
  TOP w0.15: U4.23 v1(34.5,92.17) ; U5.25 37.77,96.19 36.62,95.05 v1(36.62,92.17)
  BOTTOM w0.15: v1(36.62,92.17) v1(34.5,92.17)
BD1: length 15.1
  TOP w0.15: U4.22 29.39,91.53 29.09,91.83 29.09,93.24 32.78,96.92 v1(35.16,96.92) ; U5.24 38.19,97.46 v1(37.66,96.92)
  BOTTOM w0.15: v1(37.66,96.92) v1(35.16,96.92)
BD2: length 27.7
  TOP w0.15: U4.20 29.02,90.26 28.8,90.48 28.8,103.21 29.59,104 32.18,104 37.45,98.73 U5.23
BD3: length 17.8
  TOP w0.15: U4.19 v1(33.67,89.63) ; U5.22 v1(37.78,100)
  BOTTOM w0.15: v1(33.67,89.63) 33.67,96.54 37.13,100 v1(37.78,100)
BD4: length 21
  TOP w0.15: U5.21 v1(37.81,101.27) ; U4.17 v1(34.41,88.36)
  BOTTOM w0.15: v1(34.41,88.36) 38.51,92.47 38.51,100.56 v1(37.81,101.27)
BD5: length 30
  TOP w0.15: U5.20 37.49,102.54 35.72,104.31 29.45,104.31 27.93,102.78 27.93,88.61 28.82,87.72 U4.16
BD6: length 31.5
  TOP w0.15: U4.14 29.02,86.45 27.63,87.84 27.63,102.95 29.28,104.61 37.18,104.61 37.98,103.81 U5.19
BD7: length 31.8
  TOP w0.15: U4.13 v1(40.2,85.82) ; U5.18 v1(41.69,105.08)
  BOTTOM w0.15: v1(40.2,85.82) 40.2,103.58 v1(41.69,105.08)
BD8: length 29.9
  TOP w0.15: U3.2 35.11,55.83 v1(35.21,55.93) ; U1.12 31.41,35.68 31.56,35.83 34.82,35.83 35.21,36.22 v1(35.21,37.73)
  BOTTOM w0.15: v1(35.21,55.93) v1(35.21,37.73)
BD9: length 28.5
  TOP w0.15: U1.11 v1(33.75,35.05) ; v1(33.75,56.56) 33.65,56.47 U3.3
  BOTTOM w0.15: v1(33.75,35.05) v1(33.75,56.56)
BD10: length 27.7
  TOP w0.15: U3.5 v1(31.85,57.74) ; U1.9 v1(31.85,33.78)
  BOTTOM w0.15: v1(31.85,33.78) 31.13,34.49 31.13,57.02 v1(31.85,57.74)
BD11: length 30.7
  TOP w0.15: U1.8 v1(27.59,33.14) ; U3.6 v1(27.81,58.37)
  BOTTOM w0.15: v1(27.81,58.37) 27.3,57.86 27.3,34.24 27.59,33.95 v1(27.59,33.14)
BD12: length 35.1
  TOP w0.15: v1(25.93,43.51) 24.77,42.34 24.77,34.92 27.82,31.87 U1.6 ; v1(25.93,56.1) 25.93,57.65 27.93,59.64 U3.8
  BOTTOM w0.15: v1(25.93,56.1) v1(25.93,43.51)
BD13: length 33.1
  TOP w0.15: U3.9 v1(31.85,60.28) ; U1.5 v1(31.85,31.24)
  BOTTOM w0.15: v1(31.85,60.28) 30.84,59.26 30.84,32.25 v1(31.85,31.24)
BD14: length 37.1
  TOP w0.15: U1.3 v1(33.01,29.97) ; U3.11 v1(33.01,61.55)
  BOTTOM w0.15: v1(33.01,29.97) v1(33.01,61.55)
BD15: length 39.6
  TOP w0.15: U3.12 v1(27.11,62.18) ; U1.2 v1(26.76,29.33)
  BOTTOM w0.15: v1(27.11,62.18) 26.76,61.84 v1(26.76,29.33)
BNC2: length 17.4
  TOP w0.15: J2.1 109.92,35.92 109.92,35.5 ; 109.92,35.5 109.92,30.81 111.23,29.5 C5.1 ; 109.92,35.5 L1.2
BNC3: length 20.8
  TOP w0.15: J3.1 105.54,18.5 L2.2 ; C6.1 v1(110.68,9.58)
  BOTTOM w0.15: J3.1 111.5,10.4 v1(110.68,9.58)
BRD: length 61.1
  TOP w0.15: v1(62.16,90.12) 62.16,106.92 66.66,111.43 U5.73
  BOTTOM w0.15: v1(62.16,90.12) 53.55,90.12 46.31,82.88 46.31,70.26 U2.16
BRESET: length 58.9
  TOP w0.15: v1(38.24,114.07) 38.24,113.23 38.77,112.7 U5.12
  BOTTOM w0.15: U2.15 45.41,71.9 45.41,104.73 48.38,107.71 48.38,112.67 46.99,114.07 v1(38.24,114.07)
BWR: length 44.7
  TOP w0.15: v1(63.62,88.78) 65.11,87.3 U5.54
  BOTTOM w0.15: U2.17 46.91,68.32 46.91,82.94 52.75,88.78 v1(63.62,88.78)
D0: length 40.3
  TOP w0.15: 20.75,69.17 v1(19.15,69.17) ; U4.37 18.89,85.18 v1(17.99,84.28)
  BOTTOM w0.15: v1(19.15,69.17) 19.88,69.9 19.88,82.25 19.09,83.04 17.99,83.04 ; 17.99,83.04 17.69,82.74 6.53,82.74 5.69,83.58 5.69,88.07 J1.28 ; 17.99,83.04 v1(17.99,84.28)
D1: length 37.4
  TOP w0.15: U3.27 v1(23.3,68.53) ; U4.38 20.84,84.45 v1(22.56,84.45)
  BOTTOM w0.15: v1(23.3,68.53) 23.3,83.72 v1(22.56,84.45) 21.59,85.42 7.82,85.42 J1.27
D2: length 36.1
  TOP w0.15: U3.29 v1(22.34,67.26) ; U4.40 v1(22.34,83.28)
  BOTTOM w0.15: J1.26 7.82,85.12 20.5,85.12 v1(22.34,83.28) v1(22.34,67.26)
D3: length 33.1
  TOP w0.15: v1(16.86,80.45) 16.86,81.6 18,82.74 19.49,82.74 19.59,82.64 U4.41 ; v1(16.86,68.23) 18.46,66.63 U3.30
  BOTTOM w0.15: J1.25 7.97,80.19 12.82,80.19 13.08,80.45 v1(16.86,80.45) v1(16.86,68.23)
D4: length 41.9
  TOP w0.15: U4.43 19.59,81.37 19.48,81.27 v1(17.68,81.27) ; U3.32 17.83,65.36 v1(16.13,67.06)
  BOTTOM w0.15: v1(17.68,81.27) 17.68,67.81 16.94,67.06 v1(16.13,67.06) 16.13,73.5 11.94,77.69 7.93,77.69 J1.24
D5: length 41
  TOP w0.15: v1(21.22,73.95) 22.2,74.93 22.2,80.52 21.98,80.74 U4.44 ; v1(14.96,66.33) 16.42,64.87 19.44,64.87 19.59,64.72 U3.33
  BOTTOM w0.15: J1.23 8.91,74.17 8.91,72.61 11.45,70.07 12.04,70.07 14.96,67.15 v1(14.96,66.33) 18.3,66.33 21.22,69.25 v1(21.22,73.95)
D6: length 39
  TOP w0.15: U3.35 19.59,63.45 19.49,63.35 15.36,63.35 13.62,65.1 11.41,65.1 9.87,66.64 9.87,73.84 ; 9.87,73.84 10.99,74.96 19.09,74.96 21.91,77.77 21.91,79.17 21.61,79.47 U4.46 ; 9.87,73.84 J1.22
D7: length 42.9
  TOP w0.15: J1.21 5.69,71.3 ; 5.69,71.3 5.69,74.26 6.68,75.26 13.32,75.26 16.99,78.93 19.49,78.93 19.59,78.83 U4.47 ; 5.69,71.3 5.69,65.71 6.6,64.8 12.35,64.8 14.33,62.82 U3.36
D8: length 19.8
  TOP w0.15: U1.36 v1(18.82,36.32)
  GND w0.15: v1(18.82,36.32) 14.88,36.32 13.51,34.95 13.51,30.91 11.98,29.38 7.96,29.38 J1.4
D9: length 26.6
  TOP w0.15: U1.35 v1(22.34,36.95)
  BOTTOM w0.15: J1.5 7.98,29.38 13.12,29.38 13.57,28.93 22.44,28.93 23.07,29.57 23.07,36.22 v1(22.34,36.95)
D10: length 17.8
  TOP w0.15: U1.33 19.59,38.22 19.49,38.32 18.4,38.32 17,36.92 v1(17,34.21)
  BOTTOM w0.15: v1(17,34.21) 7.71,34.21 J1.6
D11: length 19.3
  TOP w0.15: v1(16.4,39.59) 17.23,38.76 19.49,38.76 19.59,38.86 U1.32
  BOTTOM w0.15: J1.7 5.69,36.75 5.69,38.7 6.68,39.7 16.29,39.7 v1(16.4,39.59)
D12: length 18.5
  TOP w0.15: U1.30 v1(22.34,40.13)
  BOTTOM w0.15: J1.8 7.82,39.4 13.92,39.4 14.56,38.76 20.97,38.76 v1(22.34,40.13)
D13: length 15.1
  TOP w0.15: v1(17.22,40.66) 19.49,40.66 19.59,40.76 U1.29
  BOTTOM w0.15: v1(17.22,40.66) 13.68,40.66 12.4,41.94 7.82,41.94 J1.9
D14: length 14.6
  TOP w0.15: v1(13.83,42.18) 19.44,42.18 19.59,42.03 U1.27
  BOTTOM w0.15: v1(13.83,42.18) 13.76,42.24 7.82,42.24 J1.10
D15: length 18.6
  TOP w0.15: 20.75,42.67 v1(22.34,42.67)
  BOTTOM w0.15: J1.11 7.93,44.67 20.33,44.67 v1(22.34,42.67)
DATA: length 19.2
  TOP w0.15: U5.14 v1(34.6,110.16)
  BOTTOM w0.15: U7.1 34.6,102.6 v1(34.6,110.16)
DCLK: length 23
  TOP w0.15: U5.10 v1(42.57,112.31)
  BOTTOM w0.15: U7.2 32.67,103.21 32.67,109.39 35.59,112.31 v1(42.57,112.31)
DDIR: length 98.1
  TOP w0.15: v1(24.03,57.4) 24.03,55.5 23.73,55.2 ; 23.73,55.2 U3.48 ; 23.73,55.2 24.46,54.47 41.38,54.47 42.87,55.96 U2.20 ; 20.75,92.8 v1(23.2,92.8) ; U1.48 v1(24.11,28.7)
  BOTTOM w0.15: v1(23.2,92.8) 24.03,91.98 v1(24.03,57.4) 24.76,56.66 24.76,43.55 26.23,42.08 26.23,40.89 24.11,38.76 v1(24.11,28.7)
DEN: length 82.6
  TOP w0.15: U4.24 30.97,92.8 31.69,93.52 32.36,93.52 v1(32.94,92.95) ; 30.25,28.7 v1(38.77,28.7)
  BOTTOM w0.15: 38.77,53.82 39.07,54.12 U2.21 ; 38.77,53.82 v1(38.77,28.7) ; 38.77,53.82 37.61,54.99 37.61,83.55 32.94,88.21 v1(32.94,92.95)
DHEN: length 17.3
  TOP w0.15: 30.25,55.2 v1(41.04,55.2)
  BOTTOM w0.15: U2.22 44.05,52.76 44.05,54.19 43.04,55.2 v1(41.04,55.2)
FPGA: length 31.2
  TOP w0.15: U5.30 v1(42.23,89.84)
  BOTTOM w0.15: v1(42.23,89.84) 42.23,89.03 41.79,88.59 41.79,62.82 U2.18
GAIN: length 120.7
  TOP w0.15: U5.28 v1(41.69,92.38) ; v1(85.94,47.93) 86.75,47.93 90.5,44.18 90.5,43.13 91.27,42.37 U10.6 ; U13.6 v1(94.48,22.44)
  GND w0.15: v1(41.69,92.38) 40.96,91.65 40.96,67.46 60.49,47.93 v1(85.94,47.93)
  BOTTOM w0.15: v1(85.94,47.93) 85.94,30.98 v1(94.48,22.44)
HS: length 34.5
  TOP w0.15: U5.29 v1(41.69,91.11)
  BOTTOM w0.15: U2.19 41.49,60.58 41.49,90.91 v1(41.69,91.11)
LED1: length 32.8
  TOP w0.15: D1.C 86.85,61 86.85,62 86.58,62 86.58,61 86.3,61 86.3,62 86.02,62 86.02,61 85.75,61 85.75,62 85.47,62 85.47,61 85.19,61 85.19,62 84.91,62 84.91,61 84.64,61 84.64,62 84.36,62 84.36,61 84.08,61 84.08,62 83.81,62 83.81,61 83.53,61 83.53,62 83.25,62 83.25,61 82.97,61 82.97,62 82.7,62 82.7,61 82.42,61 82.42,62 82.14,62 82.14,61 R1.2
LED2: length 32.8
  TOP w0.15: R2.2 82.11,58.5 82.11,60 82.39,60 82.39,58.5 82.66,58.5 82.66,60 82.94,60 82.94,58.5 83.22,58.5 83.22,60 83.49,60 83.49,58.5 83.77,58.5 83.77,60 84.05,60 84.05,58.5 D2.C
LED3: length 32.8
  TOP w0.15: D3.C 83.55,56 83.55,57 83.27,57 83.27,56 82.99,56 82.99,57 82.72,57 82.72,56 82.44,56 82.44,57 82.16,57 82.16,56 R3.2
LED4: length 32.8
  TOP w0.15: D4.C R4.2
MCLK: length 49.8
  TOP w0.15: U5.31 v1(42.83,88.57)
  VCC w0.15: v1(42.83,88.57) 42.83,75.75 38.65,71.57 14.59,71.57 J1.52
MEMORY.RA0: length 168.1
  TOP w0.15: U20.5 102.56,70.27 100.27,72.56 v1(93.66,72.56) ; U21.5 102.56,83.31 ; 102.56,83.31 102.23,83.63 97.65,83.63 v1(93.66,79.64) ; 102.56,83.31 v1(103.36,83.31) ; U23.5 102.56,106.61 103.3,105.88 103.3,104.88 103.19,104.78 103.19,101.09 v1(103.98,100.3) ; 102.25,96.99 102.63,97.36 v1(104.26,97.36) ; 102.25,96.99 96.69,96.99 93.55,93.84 93.55,93.22 93.42,93.09 82.37,93.09 82.23,93.23 82.23,95.62 v1(81.3,96.56) 81.22,96.63 79.45,96.63 79.06,96.23 U18.5 ; 102.25,96.99 102.56,96.69 U22.5 ; v1(79.35,108.82) 79.35,107.58 U19.5 ; U5.79 v1(61.62,112.31) ; U17.5 79.06,81.67 79.85,82.47 80.8,82.47 80.96,82.31 80.96,76.66 81.45,76.17 v1(81.45,71.06) ; v1(78.83,71.06) 79.06,70.84 U16.5
  BOTTOM w0.15: v1(78.83,71.06) v1(81.45,71.06) 92.16,71.06 v1(93.66,72.56) v1(93.66,79.64) ; v1(61.62,112.31) 64.87,115.56 76.82,115.56 77.25,115.13 77.25,114.99 78.52,113.72 78.52,109.66 v1(79.35,108.82) 81.45,106.72 81.45,101.47 80.05,100.07 80.05,97.8 v1(81.3,96.56) ; v1(103.98,100.3) 103.55,99.86 103.55,98.07 v1(104.26,97.36) 104.26,96.55 104.56,96.25 104.56,88.39 103.25,87.08 103.25,83.43 v1(103.36,83.31)
MEMORY.RA1: length 184
  TOP w0.15: U5.78 62.89,115.22 63.73,116.06 71.6,116.06 72.62,115.04 72.62,112.72 75.88,109.46 75.88,106.31 76.4,105.8 77.03,105.8 ; v1(78.31,75.28) 78.31,78.91 77.78,79.42 U17.4 ; U16.4 v1(77.78,69.9) ; U18.4 77.78,96.03 v1(78.09,96.33) ; 77.03,105.8 77.56,105.8 77.78,106.02 U19.4 ; 77.03,105.8 77.03,104.91 77.15,104.8 77.15,102.73 76.65,102.23 73.87,102.23 71.66,104.44 66.87,104.44 66.77,104.34 65.69,104.34 64.8,103.46 64.8,89.92 v1(66.15,88.57) ; v1(100.85,79.66) 100.85,80.85 U21.4 ; U23.4 101.28,106.02 101.81,105.5 101.81,104.91 101.92,104.8 101.92,101.36 v1(101.18,100.62) ; U20.4 v1(101.28,69.9) ; v1(101.18,95.9) 101.18,94.38 U22.4
  GND w0.15: v1(78.31,75.28) 73.75,75.28 72.99,76.04 72.99,82.75 67.18,88.57 v1(66.15,88.57)
  BOTTOM w0.15: v1(78.09,96.33) 78.09,88.25 78.52,87.82 78.52,76.3 78.31,76.09 v1(78.31,75.28) 77.78,74.76 v1(77.78,69.9) 78.82,68.87 100.25,68.87 v1(101.28,69.9) 100.85,70.33 v1(100.85,79.66) 100.85,84.03 100.45,84.43 100.45,95.17 v1(101.18,95.9) v1(101.18,100.62)
MEMORY.RA2: length 152.9
  TOP w0.15: U18.3 76.22,94.58 v1(76.22,96.03) ; U17.3 76.52,82.36 v1(75.98,82.9) ; v1(99.69,99.43) 99.69,100.25 99.28,100.65 99.28,102.57 99.38,102.66 99.38,105 100.02,105.64 U23.3 ; v1(100.02,69.9) U20.3 100.02,67.02 96.86,63.86 79.67,63.86 76.52,67.02 U16.3 76.52,70.83 v1(75.98,71.37) ; U21.3 v1(100.02,82.9) ; 64.16,112.74 64.55,112.74 v1(65.12,112.16) ; 64.16,112.74 62.61,112.74 62.26,113.09 62.26,115.62 62.99,116.36 71.78,116.36 72.92,115.22 72.92,113.86 76.52,110.26 U19.3 ; 64.16,112.74 U5.77 ; v1(99.69,96.26) 100.02,95.93 U22.3
  GND w0.15: v1(65.12,112.16) 65.12,107.12 v1(76.22,96.03)
  BOTTOM w0.15: v1(75.98,71.37) v1(75.98,82.9) 75.98,83.71 75.78,83.91 75.78,87.86 76.22,88.3 v1(76.22,96.03) ; v1(99.69,99.43) v1(99.69,96.26) 99.69,95.44 100.08,95.05 100.08,82.96 v1(100.02,82.9) v1(100.02,69.9)
MEMORY.RA3: length 158.3
  TOP w0.15: v1(98.75,105.64) U23.2 ; U21.2 98.75,81.67 97.94,82.47 97.03,82.47 96.52,81.96 v1(96.52,77.3) ; v1(97.79,95.9) 98.6,95.9 98.75,95.76 U22.2 ; U5.76 65.43,115.22 65.97,115.76 71.43,115.76 72.32,114.87 72.32,112.36 74.51,110.17 v1(74.51,108.9) 74.51,107.41 74.65,107.28 U19.2 ; U18.2 74.65,94.28 74.51,94.41 v1(74.51,95.9) ; U16.2 v1(75.25,69.9) 75.25,71.7 75.64,72.1 76.4,72.1 77.03,71.46 77.03,69.47 77.15,69.35 77.15,67.27 79.96,64.46 91.76,64.46 97.2,69.9 v1(98.01,69.9) 98.01,68.41 98.14,68.28 U20.2 ; v1(75.25,79.41) U17.2
  BOTTOM w0.15: v1(98.75,105.64) 98.75,104.83 98.52,104.6 98.52,96.63 v1(97.79,95.9) 97.79,92.94 99.48,91.26 99.48,86.82 98.51,85.85 98.51,77.5 98.01,77 ; 98.01,77 97.71,77.3 v1(96.52,77.3) ; 98.01,77 v1(98.01,69.9) ; 75.25,75.37 v1(75.25,79.41) ; 75.25,75.37 73.64,75.37 73.24,75.77 73.24,89.5 74.51,90.77 v1(74.51,95.9) 70.88,99.53 70.88,106.61 73.16,108.9 v1(74.51,108.9) ; 75.25,75.37 v1(75.25,69.9)
MEMORY.RA4: length 146.8
  TOP w0.15: 73.45,84.03 73.45,79.77 73.97,79.25 U16.32 ; 73.45,84.03 73.32,84.03 69.42,87.94 66.87,87.94 66.77,87.83 65.77,87.83 64.5,89.11 64.5,104.72 65.9,106.11 66.74,106.11 ; 73.45,84.03 73.75,84.33 v1(74.71,84.33) ; U21.32 v1(97.47,88.44) ; U23.32 97.47,116.06 96.87,115.45 96.87,115.28 v1(97.58,114.57) ; 66.74,106.11 67.14,105.72 70.45,105.72 70.96,105.2 73.16,105.2 73.97,104.39 U18.32 ; 66.74,106.11 66.74,108.36 67.28,108.89 U5.71 69.84,108.89 71.28,110.33 v1(71.28,114.83) ; v1(97.47,79.34) U20.32 97.47,76.45 96.39,75.37 v1(86.96,75.37) ; U19.32 v1(73.97,114.83) ; v1(74.71,87.78) 73.97,88.51 U17.32 ; U22.32 97.47,105.25 96.95,105.77 96.95,108.9 v1(97.78,109.72)
  GND w0.15: v1(86.96,75.37) 78,84.33 v1(74.71,84.33)
  BOTTOM w0.15: v1(73.97,114.83) v1(71.28,114.83) ; v1(97.47,79.34) v1(97.47,88.44) 97.47,89.31 96.76,90.03 96.76,108.71 v1(97.78,109.72) 97.58,109.92 v1(97.58,114.57) ; v1(74.71,87.78) v1(74.71,84.33)
MEMORY.RA5: length 154
  TOP w0.15: U23.31 v1(98.75,114.86) ; v1(75.25,114.83) U19.31 ; U17.31 v1(75.25,89.1) ; 73.23,107.62 U5.70 ; 73.23,107.62 73.23,106.44 73.87,105.81 74.42,105.81 75.25,104.98 U18.31 ; 73.23,107.62 v1(73.23,109.63) ; U16.31 75.25,76.45 74.89,76.1 v1(73.97,76.1) ; U22.31 98.75,101.33 v1(97.64,100.22) 97.58,100.17 77.01,100.17 v1(75.55,98.7) ; U20.31 v1(98.75,75.95) ; U21.31 v1(98.75,88.97)
  BOTTOM w0.15: 75.25,109.63 75.25,108.57 74.36,107.68 72.49,107.68 71.48,106.67 71.48,102.77 v1(75.55,98.7) 75.25,98.4 v1(75.25,89.1) 74.43,89.1 73.97,88.64 v1(73.97,76.1) ; 75.25,109.63 v1(73.23,109.63) ; 75.25,109.63 v1(75.25,114.83) ; v1(98.75,114.86) 98.75,108.12 97.64,107.02 v1(97.64,100.22) 97.06,99.64 97.06,90.65 v1(98.75,88.97) 98.75,88.15 98.21,87.62 98.21,78.97 97.57,78.33 96.42,78.33 95.79,77.7 95.79,74.26 96.45,73.6 96.45,70.31 97.6,69.17 98.35,69.17 98.75,69.56 v1(98.75,75.95)
MEMORY.RA6: length 149.1
  TOP w0.15: U21.30 100.02,89.97 v1(101.18,88.8) ; U5.69 v1(72.21,106.35) 73.05,105.5 73.86,105.5 74.5,104.87 74.5,102.79 74.75,102.53 75.72,102.53 76.52,103.33 U18.30 ; v1(99.28,79.64) 99.28,77.85 99.42,77.72 U20.30 ; U22.30 v1(100.02,102.16) ; v1(76.95,79.64) 76.52,79.2 U16.30 ; v1(76.52,114.83) U19.30 76.52,117.98 76.73,118.2 80.42,118.2 80.96,117.67 80.96,115.66 81.06,115.56 81.06,115.22 85.01,111.27 86.52,111.27 87.72,112.47 89.78,112.47 90.12,112.81 v1(100.02,112.81) ; U23.30 v1(100.02,114.86) ; v1(76.52,87.05) U17.30
  BOTTOM w0.15: v1(99.28,79.64) 99.28,84.58 99.78,85.08 99.78,92.89 98.95,93.71 98.95,101.1 v1(100.02,102.16) ; v1(76.52,114.83) 76.52,106.65 ; 76.52,106.65 76.95,106.22 76.95,87.35 ; 76.52,106.65 76.22,106.35 v1(72.21,106.35) ; 76.95,87.35 76.81,87.35 v1(76.52,87.05) ; 76.95,87.35 v1(76.95,79.64) ; v1(100.02,102.16) 100.83,102.16 101.91,101.07 101.91,89.53 v1(101.18,88.8) ; v1(100.02,102.16) 100.02,112.81 v1(100.02,112.81) v1(100.02,114.86)
MEMORY.RA7: length 171.2
  TOP w0.15: v1(100.77,109.47) 100.77,105.77 101.28,105.25 U22.29 ; v1(77.14,76.1) 77.14,77.67 77.19,77.72 U16.29 ; U18.29 v1(77.78,101.22) 74.46,101.22 71.87,103.81 U5.67 ; v1(94.28,93.09) 100.17,93.09 101.28,91.98 U21.29 ; U23.29 101.28,114.47 v1(101.18,114.37) ; U19.29 v1(77.78,113.36) ; v1(102.02,75.86) 102.02,77.59 101.89,77.72 U20.29 ; U17.29 v1(77.78,87.31)
  VCC w0.15: v1(101.18,114.37) 101.18,115.18 100.62,115.74 94.44,115.74 92.79,114.09 92.79,103.88 93.55,103.13 93.55,99.43 92.81,98.7 ; 92.81,98.7 91.78,99.73 79.57,99.73 79.27,99.43 77.78,99.43 ; 92.81,98.7 92.81,94.56 v1(94.28,93.09) ; v1(77.78,87.31) 77.78,88.12 77.35,88.55 77.35,98.27 77.78,98.7 77.78,99.43 ; 77.78,99.43 v1(77.78,101.22)
  BOTTOM w0.15: v1(102.02,75.86) 102.02,69.58 101,68.57 78.07,68.57 77.05,69.58 77.05,76.01 v1(77.14,76.1) 77.78,76.75 v1(77.78,87.31) ; v1(101.18,114.37) 101.18,109.88 v1(100.77,109.47) ; v1(77.78,101.22) v1(77.78,113.36)
MEMORY.RA8: length 135.6
  TOP w0.15: 78.95,100.54 93.55,100.54 96.34,103.33 96.34,109.44 97.36,110.46 101.48,110.46 101.74,110.2 v1(102.56,110.2) ; 78.95,100.54 78.9,100.48 72.72,100.48 70.66,102.54 U5.66 ; 78.95,100.54 v1(78.95,101.27) 78.95,102.53 ; v1(102.63,88.37) 102.56,88.44 U21.28 ; U20.28 102.56,78.11 103.36,78.91 105.85,78.91 106.28,79.34 v1(107.1,79.34) ; U23.28 v1(102.56,114.86) ; U22.28 v1(102.56,105.34) ; U16.28 79.06,79.44 v1(79.28,79.66) ; 78.95,102.53 78.42,103.07 78.42,110.38 79.06,111.01 U19.28 ; 78.95,102.53 79.06,102.53 U18.28 ; U17.28 v1(79.06,89.01)
  BOTTOM w0.15: v1(79.28,79.66) 79.06,79.88 v1(79.06,89.01) 78.95,89.11 v1(78.95,101.27) ; v1(107.1,79.34) 104.54,81.89 103.65,81.89 102.63,82.91 v1(102.63,88.37) 102.63,105.26 v1(102.56,105.34) v1(102.56,110.2) v1(102.56,114.86)
MEMORY.RA9: length 144.6
  TOP w0.15: v1(79.92,84.83) 76.06,84.83 71.59,89.3 71.59,92.48 69.78,94.28 66.89,94.28 65.4,95.78 65.4,100.38 66.29,101.27 U5.65 ; U17.22 86.42,90.47 v1(86.42,89.1) ; v1(87,113.45) 86.67,113.78 U19.22 ; U21.22 v1(110.17,88.91) ; U18.22 v1(86.67,105.34) ; U20.22 v1(110.17,79.34) ; U23.22 v1(110.17,114.14) ; v1(86.95,84.83) 86.95,84.02 87.41,83.56 87.41,77.85 87.28,77.72 U16.22 ; v1(110.17,101.94) U22.22 v1(110.17,105.64)
  GND w0.15: 109.72,85.34 109.72,86.07 110.17,86.53 v1(110.17,88.91) ; 109.72,85.34 110.17,84.88 v1(110.17,79.34) ; 109.72,85.34 106.77,85.34 106.26,84.83 v1(86.95,84.83)
  BOTTOM w0.15: v1(110.17,114.14) 110.17,113.33 110.45,113.05 110.45,106.73 110.17,106.45 v1(110.17,105.64) ; v1(110.17,101.94) 110.17,101.13 110.44,100.86 110.44,89.99 110.17,89.72 v1(110.17,88.91) ; v1(87,113.45) 87,105.66 v1(86.67,105.34) 86.67,89.35 v1(86.42,89.1) 86.42,85.36 v1(86.95,84.83) 86.37,84.25 80.5,84.25 v1(79.92,84.83)
MEMORY.RA10: length 180.4
  TOP w0.15: U16.21 87.94,79.55 88.47,80.07 v1(88.47,82.9) 89.61,84.05 107.97,84.05 108.37,83.65 108.37,82.44 108.27,82.34 108.27,80.3 108.5,80.07 110.56,80.07 111.44,79.18 U20.21 v1(111.44,76.1) ; U19.21 87.94,114.91 v1(88.3,114.55) ; U17.21 87.94,89.08 v1(87.51,88.65) ; U23.21 111.44,109.44 v1(111.21,109.2) 112.08,108.33 112.08,105.88 111.44,105.25 U22.21 ; v1(87.51,102.03) 87.51,103.29 U18.21 ; v1(111.94,89.1) 111.94,90.22 U21.21 ; U5.64 v1(66.13,100)
  BOTTOM w0.15: v1(88.47,82.9) 88.47,87.69 v1(87.51,88.65) v1(87.51,102.03) 87.51,111.96 88.15,112.6 88.15,113.34 87.3,114.18 86.69,114.18 86.57,114.31 ; v1(111.44,76.1) 111.94,76.6 v1(111.94,89.1) 111.21,89.83 v1(111.21,109.2) ; v1(66.13,100) 55.51,110.62 55.51,113.84 58.12,116.46 77.19,116.46 78.15,115.5 78.15,115.49 79.9,113.74 85.99,113.74 86.56,114.31 86.57,114.31 ; v1(88.3,114.55) 86.8,114.55 86.57,114.31
MEMORY.RA11: length 161.1
  TOP w0.15: U21.20 v1(112.72,92.19) ; U18.20 v1(89.22,101.8) ; U19.20 89.22,117.39 90.03,118.2 96.27,118.2 96.78,117.7 96.78,116.47 v1(95.01,114.7) ; U16.20 v1(89.22,79.34) ; 95.01,98.12 112.31,98.12 v1(112.72,97.72) ; 95.01,98.12 94.78,97.89 77.29,97.89 77.07,97.67 74.05,97.67 72.99,98.73 U5.63 ; 95.01,98.12 v1(95.01,99.22) ; U22.20 v1(112.72,102.23) 116.71,102.23 117.34,102.87 117.34,117.51 116.95,117.91 113.52,117.91 112.72,117.11 U23.20 ; U20.20 v1(112.72,79.34) ; U17.20 v1(89.22,89.1)
  GND w0.15: 95.01,102.3 v1(95.01,99.22) ; 95.01,102.31 v1(95.01,114.7) ; 95.01,102.31 92.45,102.31 92.06,101.91 92.06,101.67 91.61,101.23 89.79,101.23 v1(89.22,101.8)
  BOTTOM w0.15: v1(112.72,102.23) v1(112.72,97.72) v1(112.72,92.19) v1(112.72,79.34) ; v1(89.22,101.8) v1(89.22,89.1) v1(89.22,79.34)
MEMORY.RA12: length 152.6
  TOP w0.15: v1(113.98,108.9) 113.35,108.26 113.35,105.62 113.98,104.98 U22.19 ; v1(96.04,117.37) 95.23,117.37 94.7,117.91 91.28,117.91 90.48,117.11 U19.19 v1(90.48,114.35) ; U18.19 90.48,102.03 90.51,102 v1(91.32,102) ; v1(91.32,98.62) 90.51,98.62 90.08,98.19 76.69,98.19 76.47,97.97 75.07,97.97 73.67,99.36 67.05,99.36 66.66,98.98 66.66,98.08 67.28,97.46 U5.62 ; v1(91.25,76.1) 90.48,76.86 U16.19 ; U20.19 113.79,77.52 v1(113.79,76.1) ; v1(91.32,88.88) 90.51,88.88 90.48,88.9 U17.19 ; U23.19 v1(113.98,115.1) ; U21.19 v1(113.98,88.18)
  BOTTOM w0.15: v1(96.04,117.37) 111.72,117.37 v1(113.98,115.1) v1(113.98,108.9) v1(113.98,88.18) 113.98,76.3 v1(113.79,76.1) ; v1(90.48,114.35) 90.48,113.53 91,113.02 91,103.14 91.32,102.82 v1(91.32,102) v1(91.32,98.62) v1(91.32,88.88) 91.25,88.8 v1(91.25,76.1)
MEMORY.RA13: length 163.9
  TOP w0.15: U17.18 91.75,90.06 92.71,89.1 v1(93.95,89.1) ; U5.61 69.22,96.19 72.19,93.23 72.19,89.24 75.11,86.31 79.46,86.31 80.33,87.18 v1(93.95,87.18) ; U18.18 v1(91.75,105.34) ; v1(92.05,79.34) 92.05,78.02 U16.18 ; U19.18 v1(91.75,114.86) ; v1(114.52,74.56) 115.25,75.29 U20.18 ; U21.18 v1(115.25,87.44) ; U22.18 115.25,104.11 116.06,104.91 116.41,104.91 117.05,105.54 117.05,110.03 116.41,110.66 v1(114.95,110.66) 115.25,110.96 U23.18
  GND w0.15: v1(114.52,74.56) 96.83,74.56 v1(92.05,79.34)
  BOTTOM w0.15: v1(114.95,110.66) 114.95,87.74 v1(115.25,87.44) 114.52,86.71 v1(114.52,74.56) ; 92.36,89.1 92.05,88.8 v1(92.05,79.34) ; 92.36,89.1 v1(93.95,89.1) v1(93.95,87.18) ; 92.36,89.1 92.06,89.4 92.06,104.23 91.75,104.53 v1(91.75,105.34) v1(91.75,114.86)
